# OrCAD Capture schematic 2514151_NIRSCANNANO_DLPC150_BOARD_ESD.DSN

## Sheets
1 PAGE-07 LAMP DRIVER: size A3
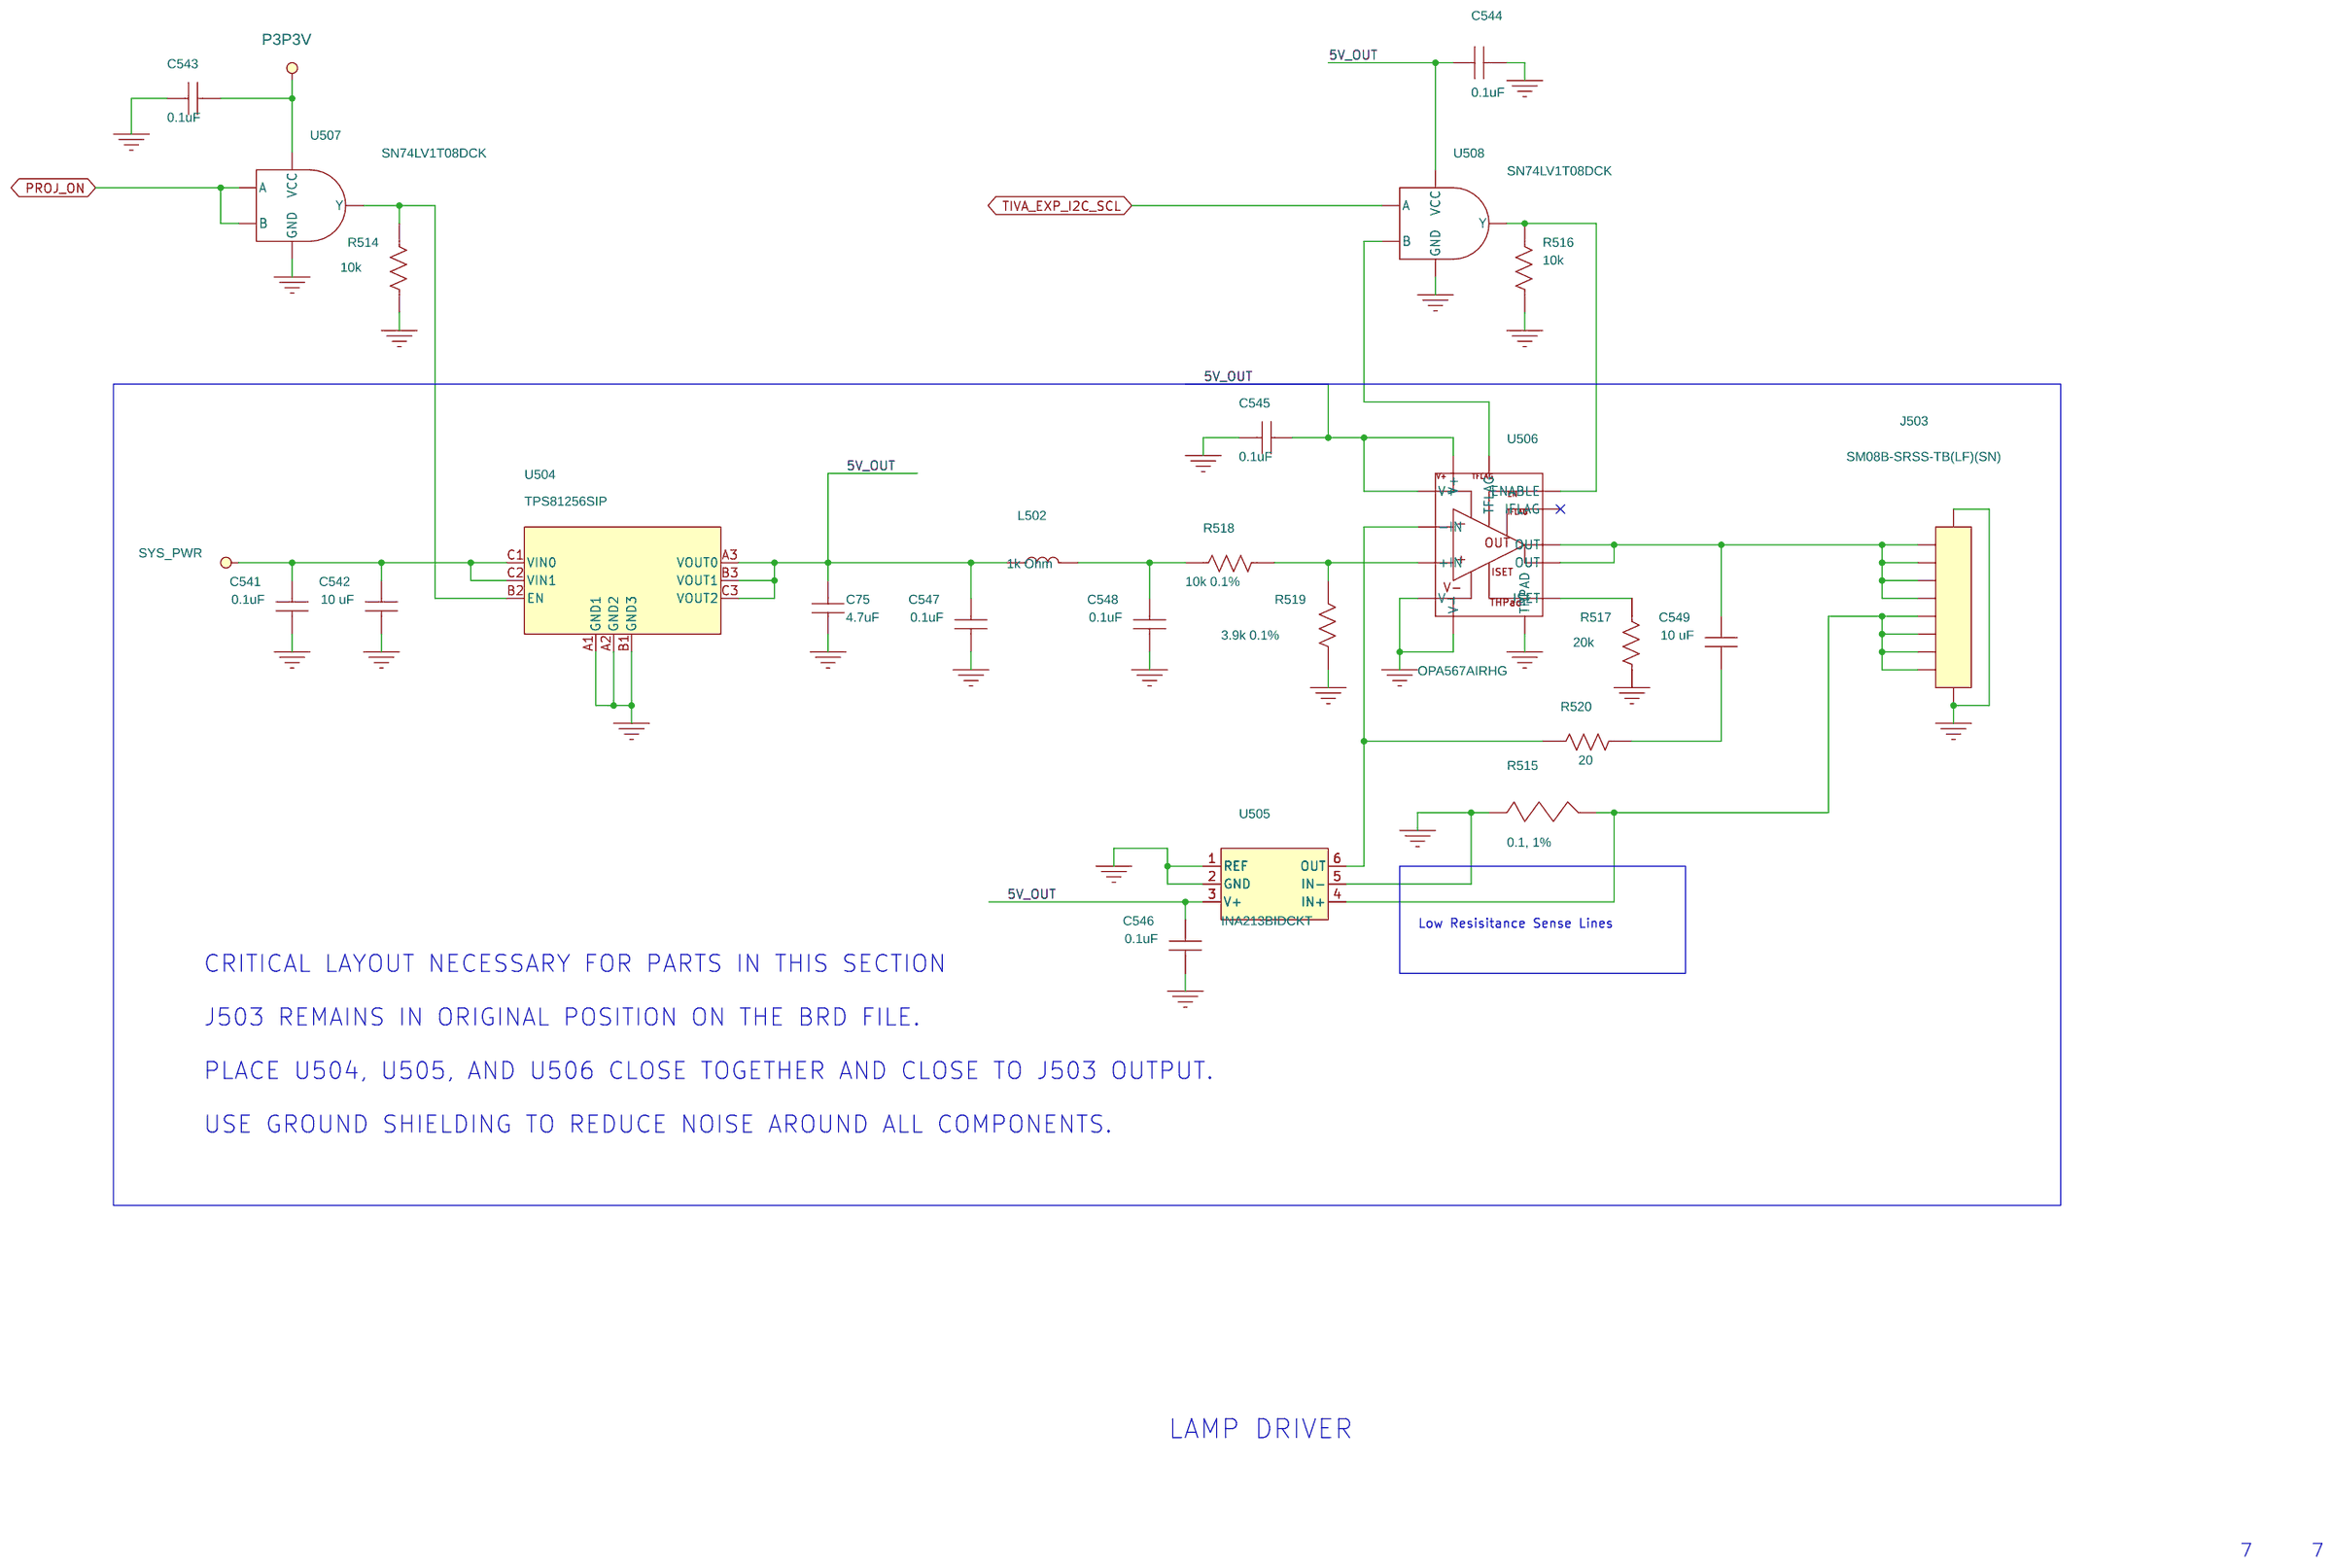
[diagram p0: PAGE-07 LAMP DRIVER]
2 PAGE-01 TITLE: title: ESD, NIRscan Nano DLPC 150 Board
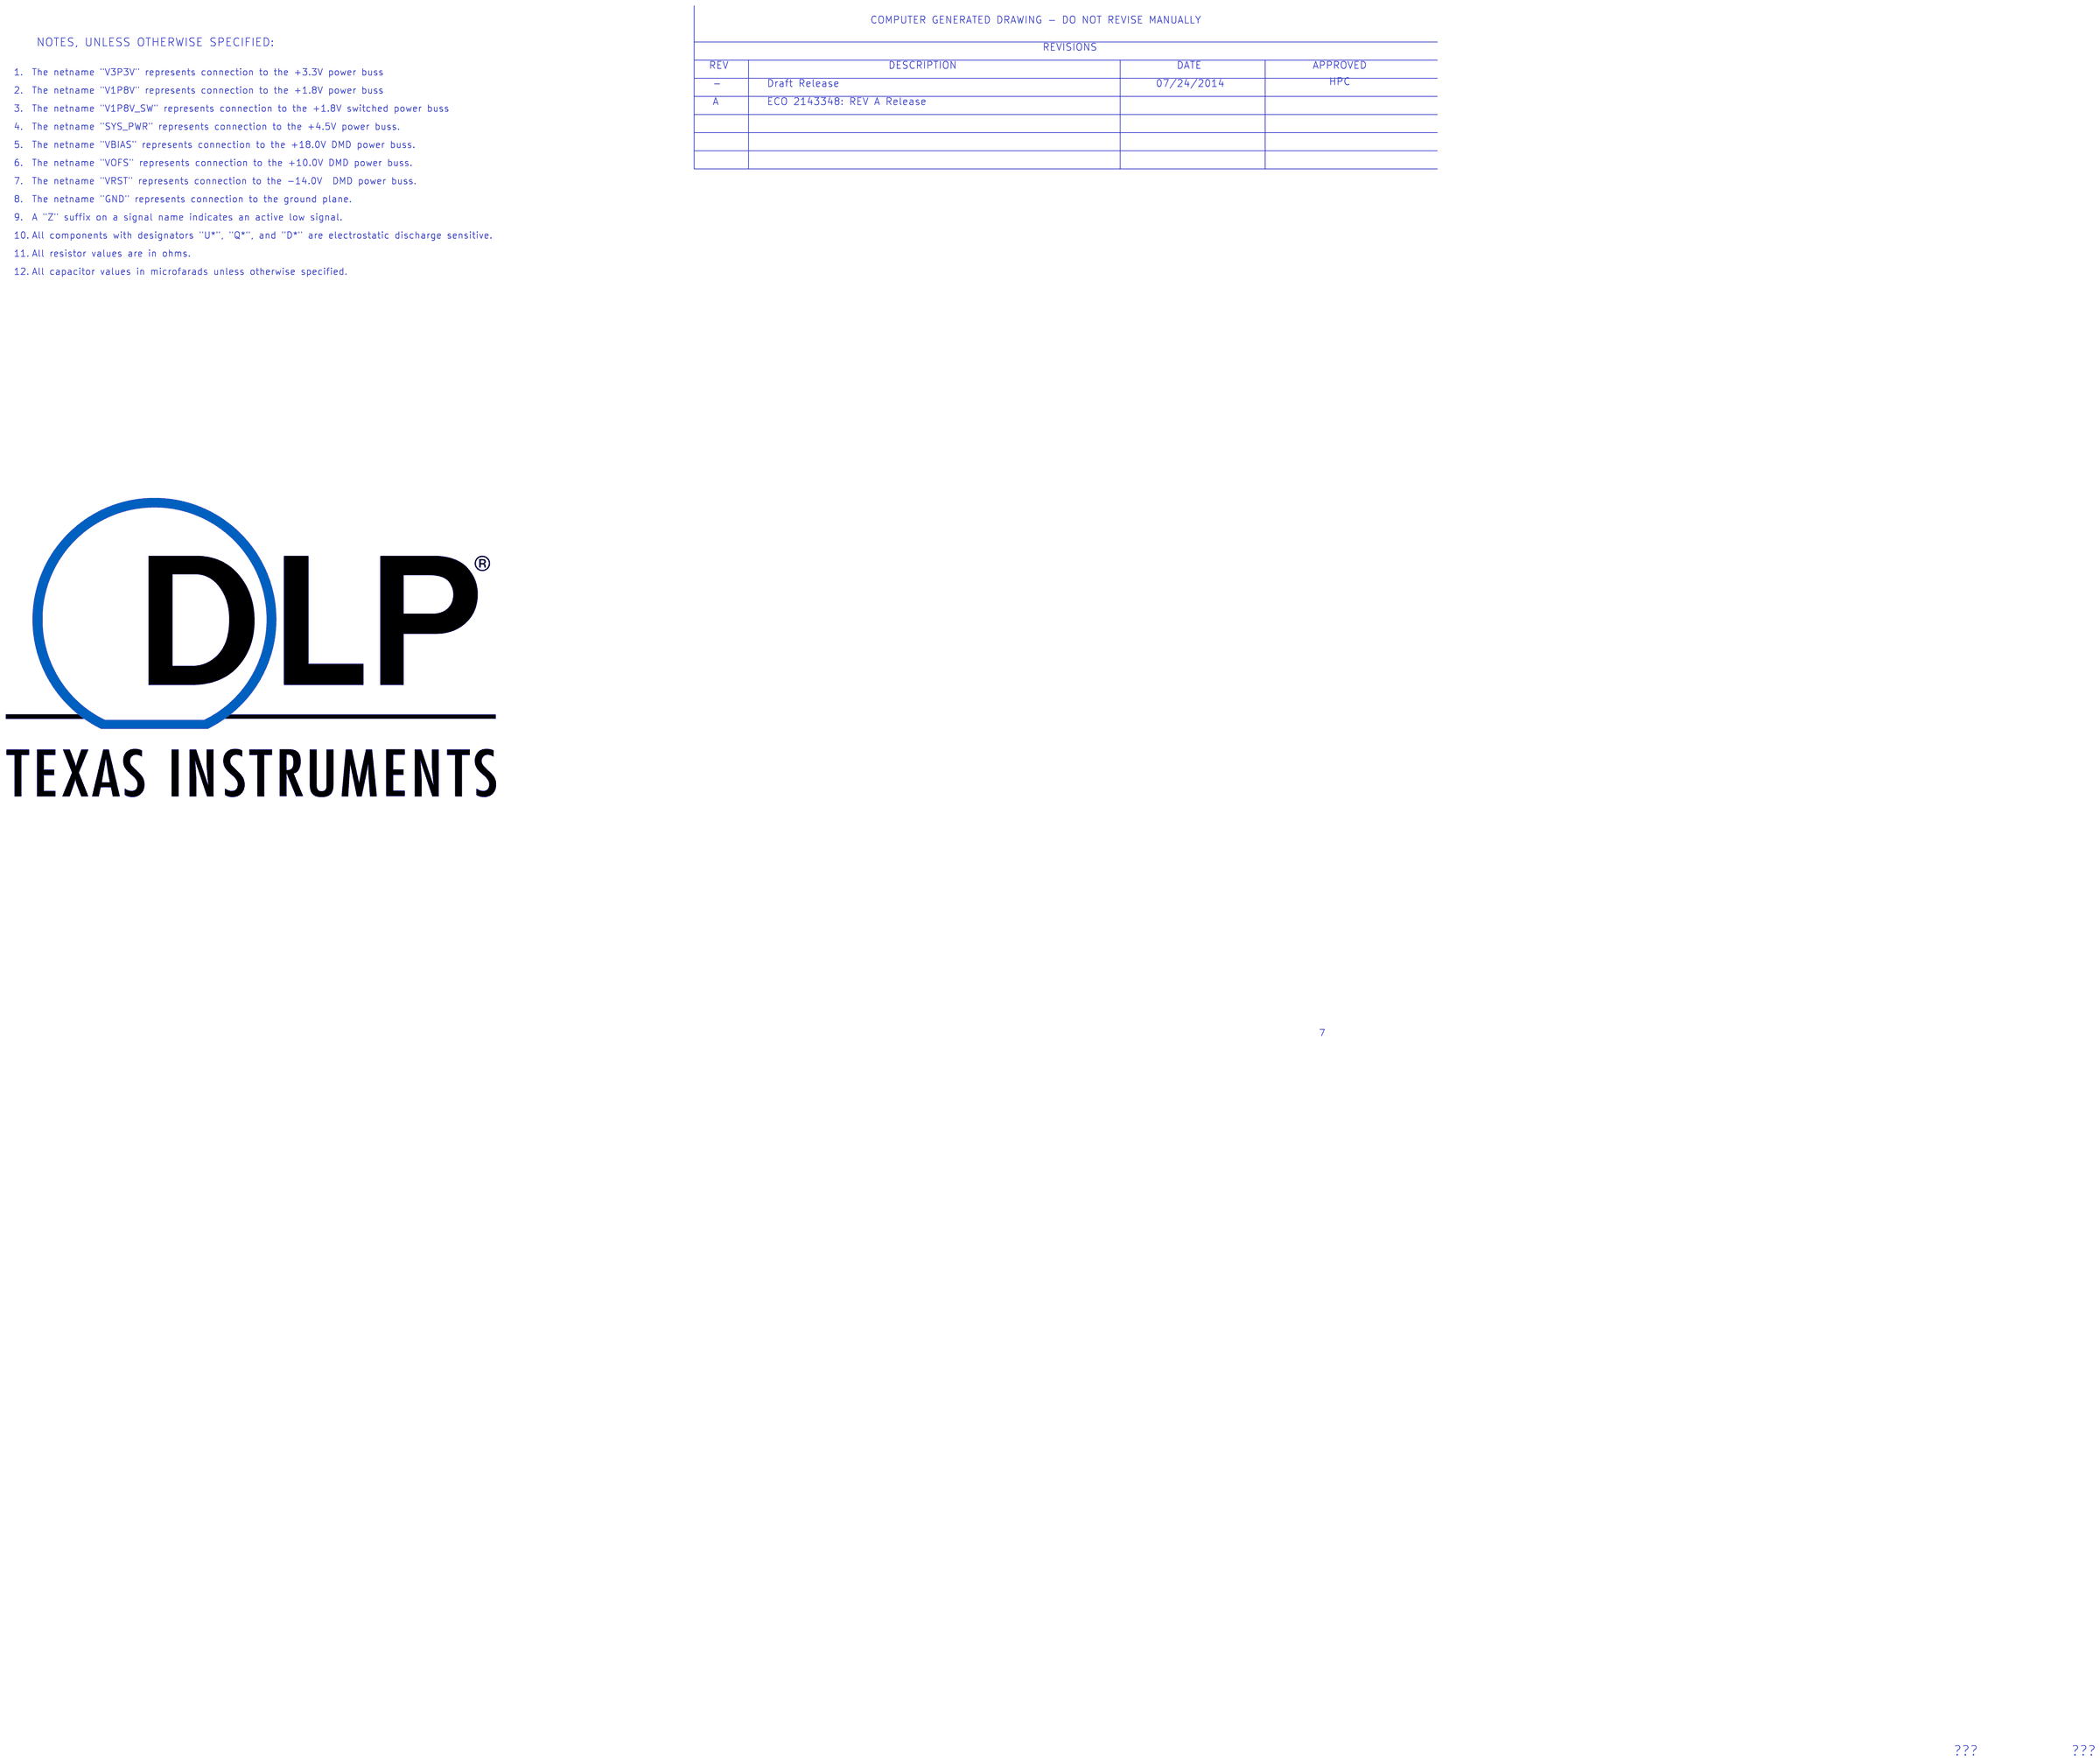
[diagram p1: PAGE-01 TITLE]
3 PAGE-02 DLPC PARALLEL & DMD: size A3
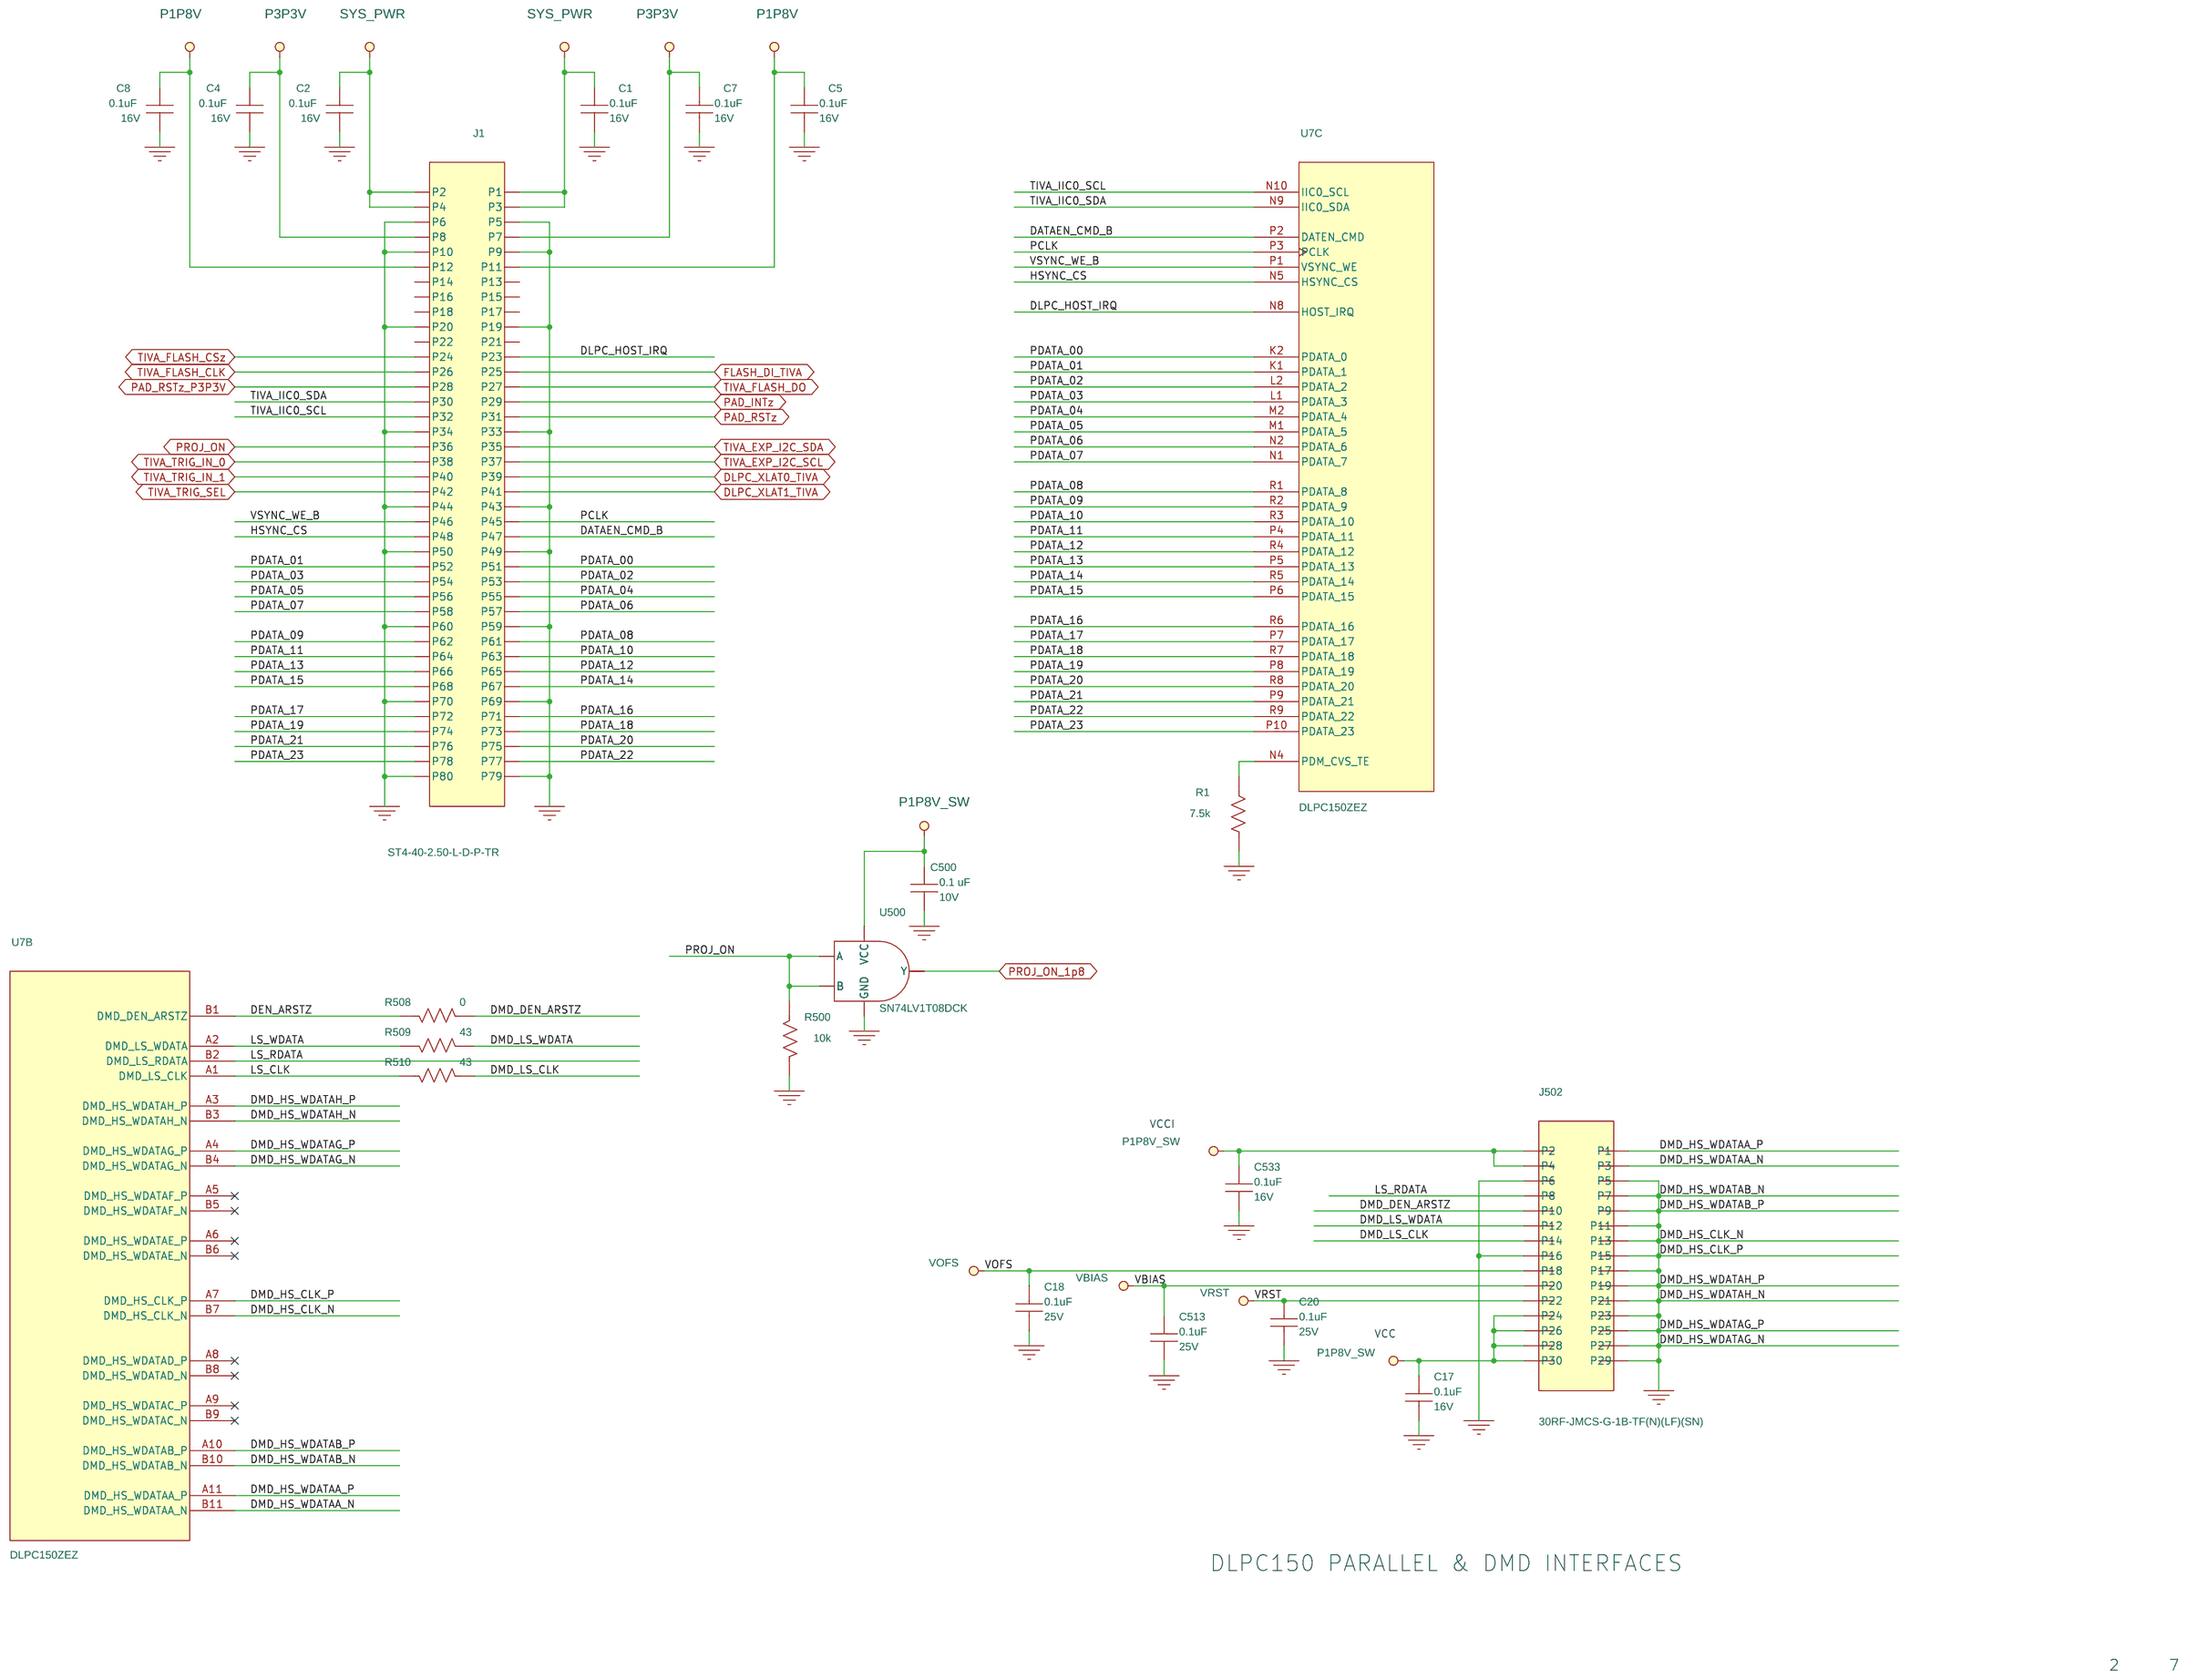
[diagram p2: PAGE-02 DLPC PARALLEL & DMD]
4 PAGE-04 DLPC POWER: size A3
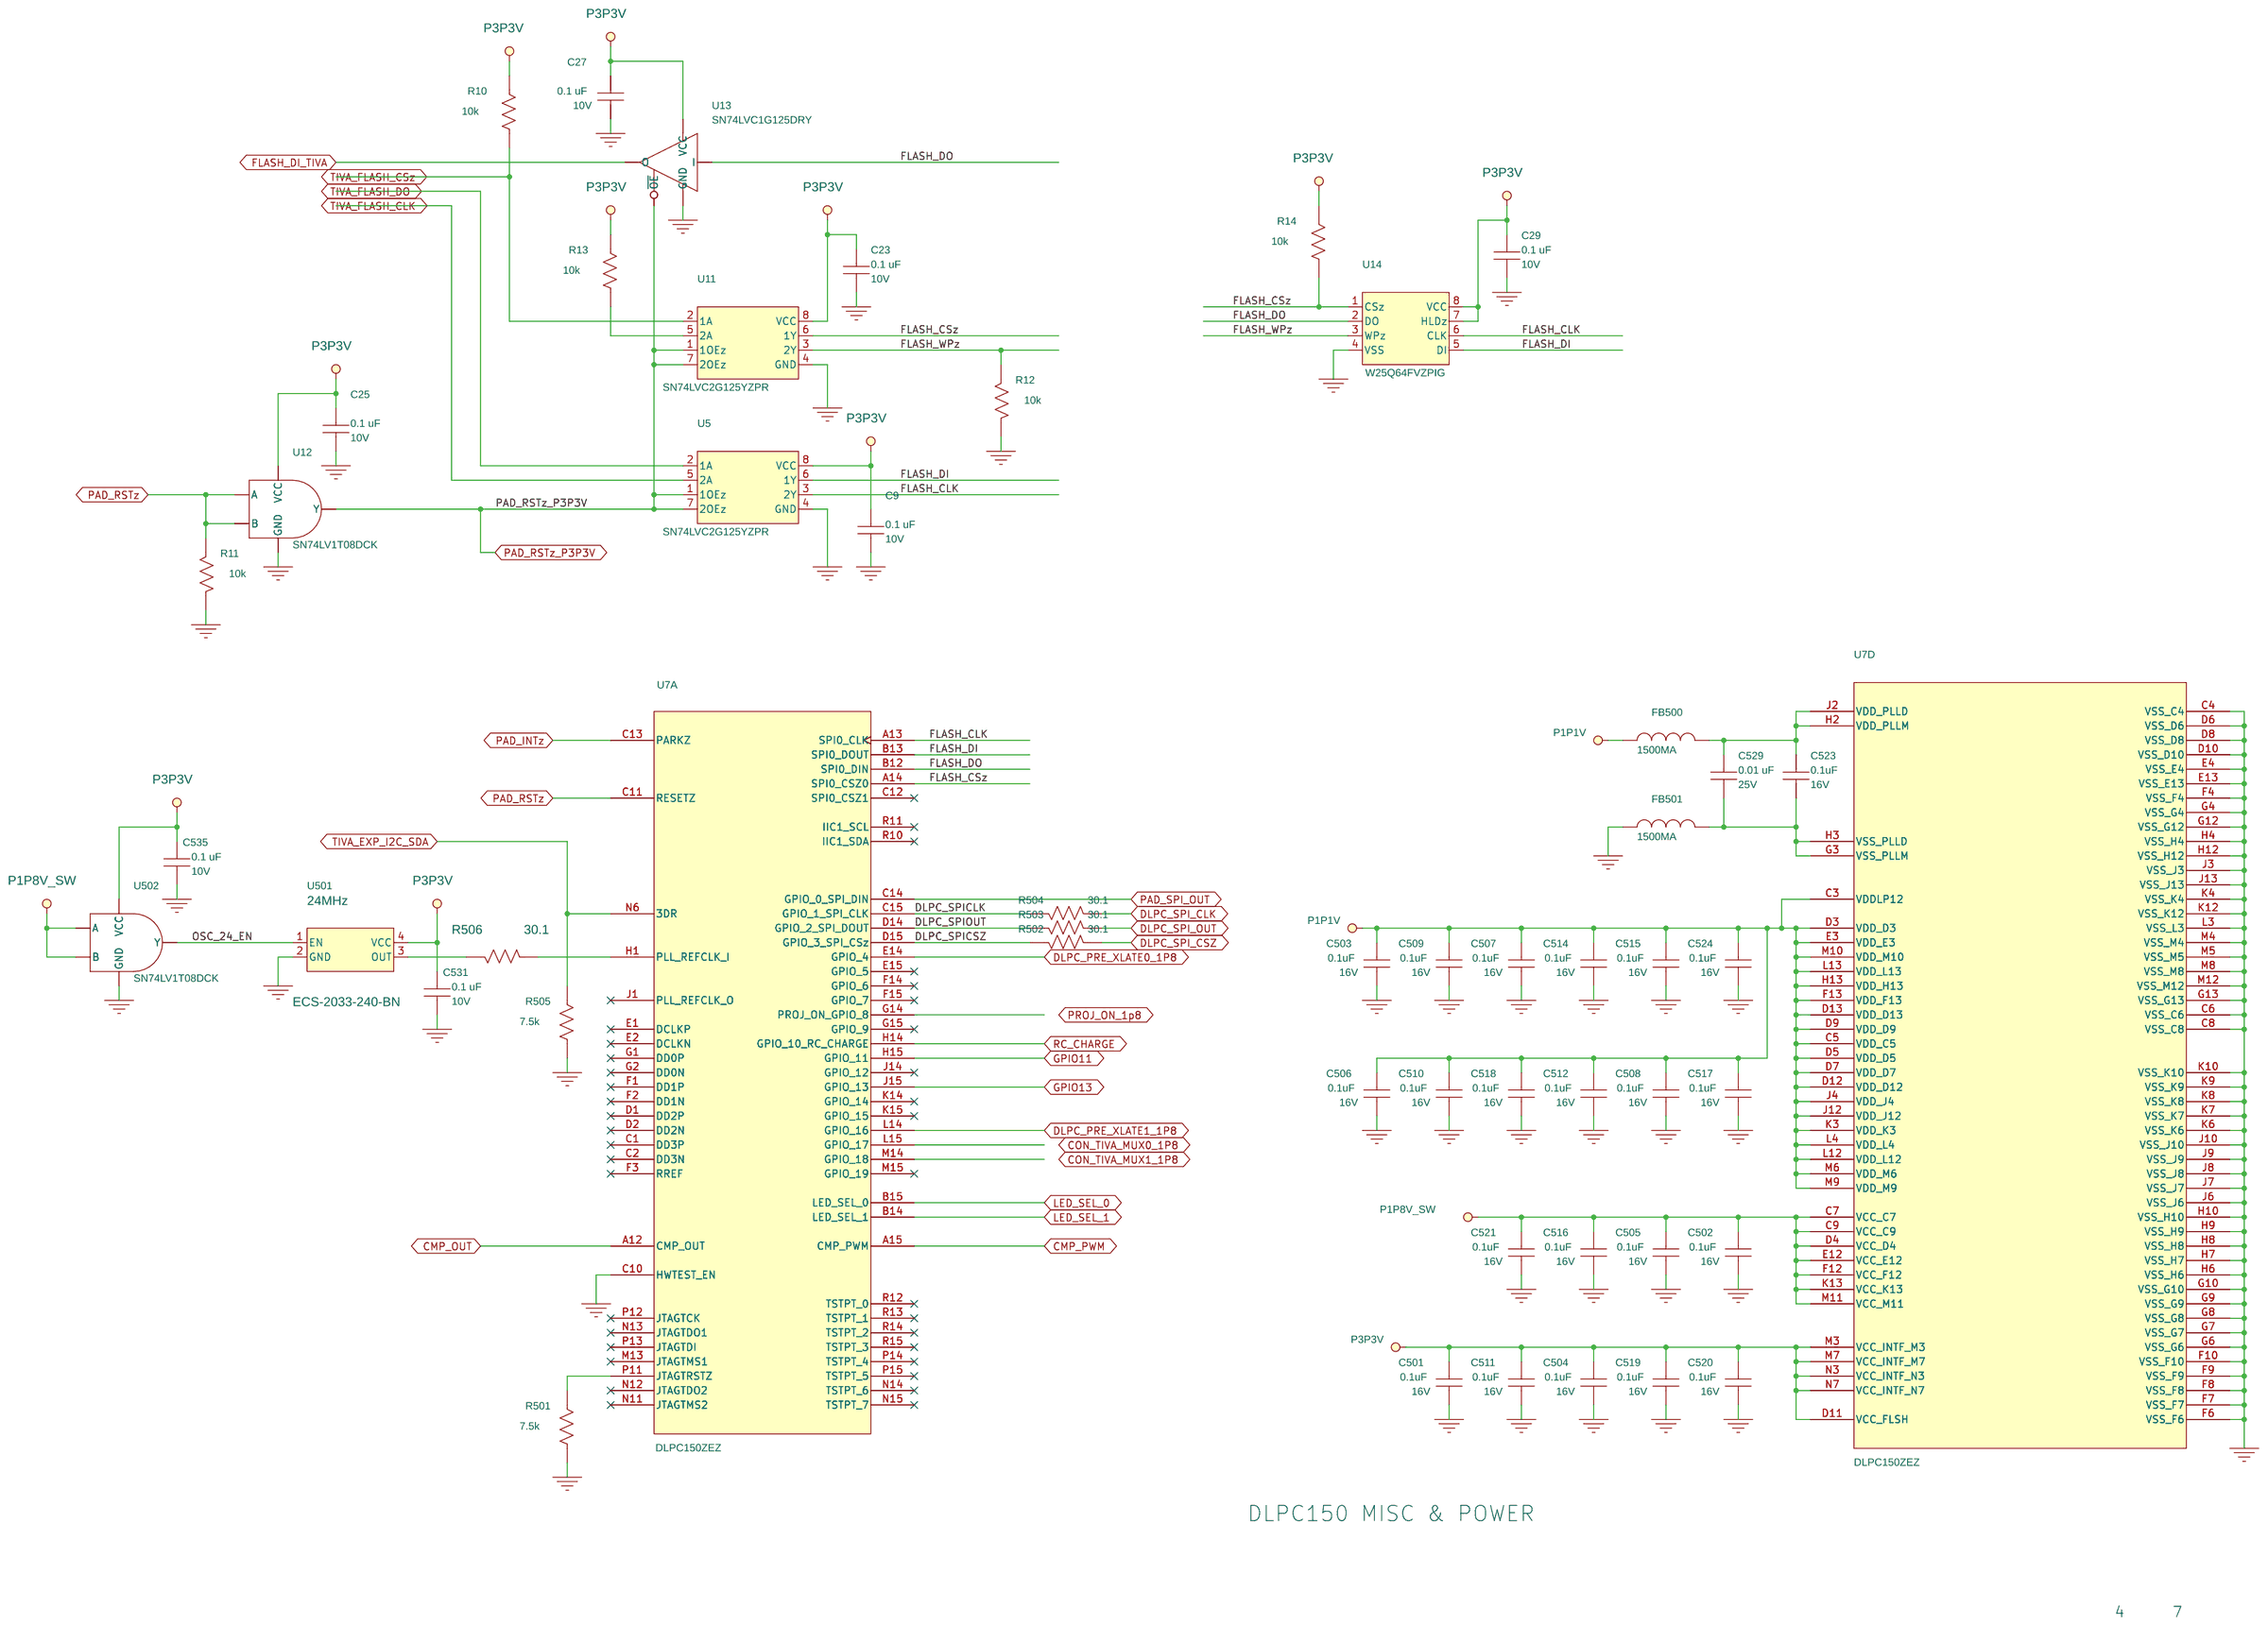
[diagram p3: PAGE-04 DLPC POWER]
5 PAGE-05 PAD_2005: size A3
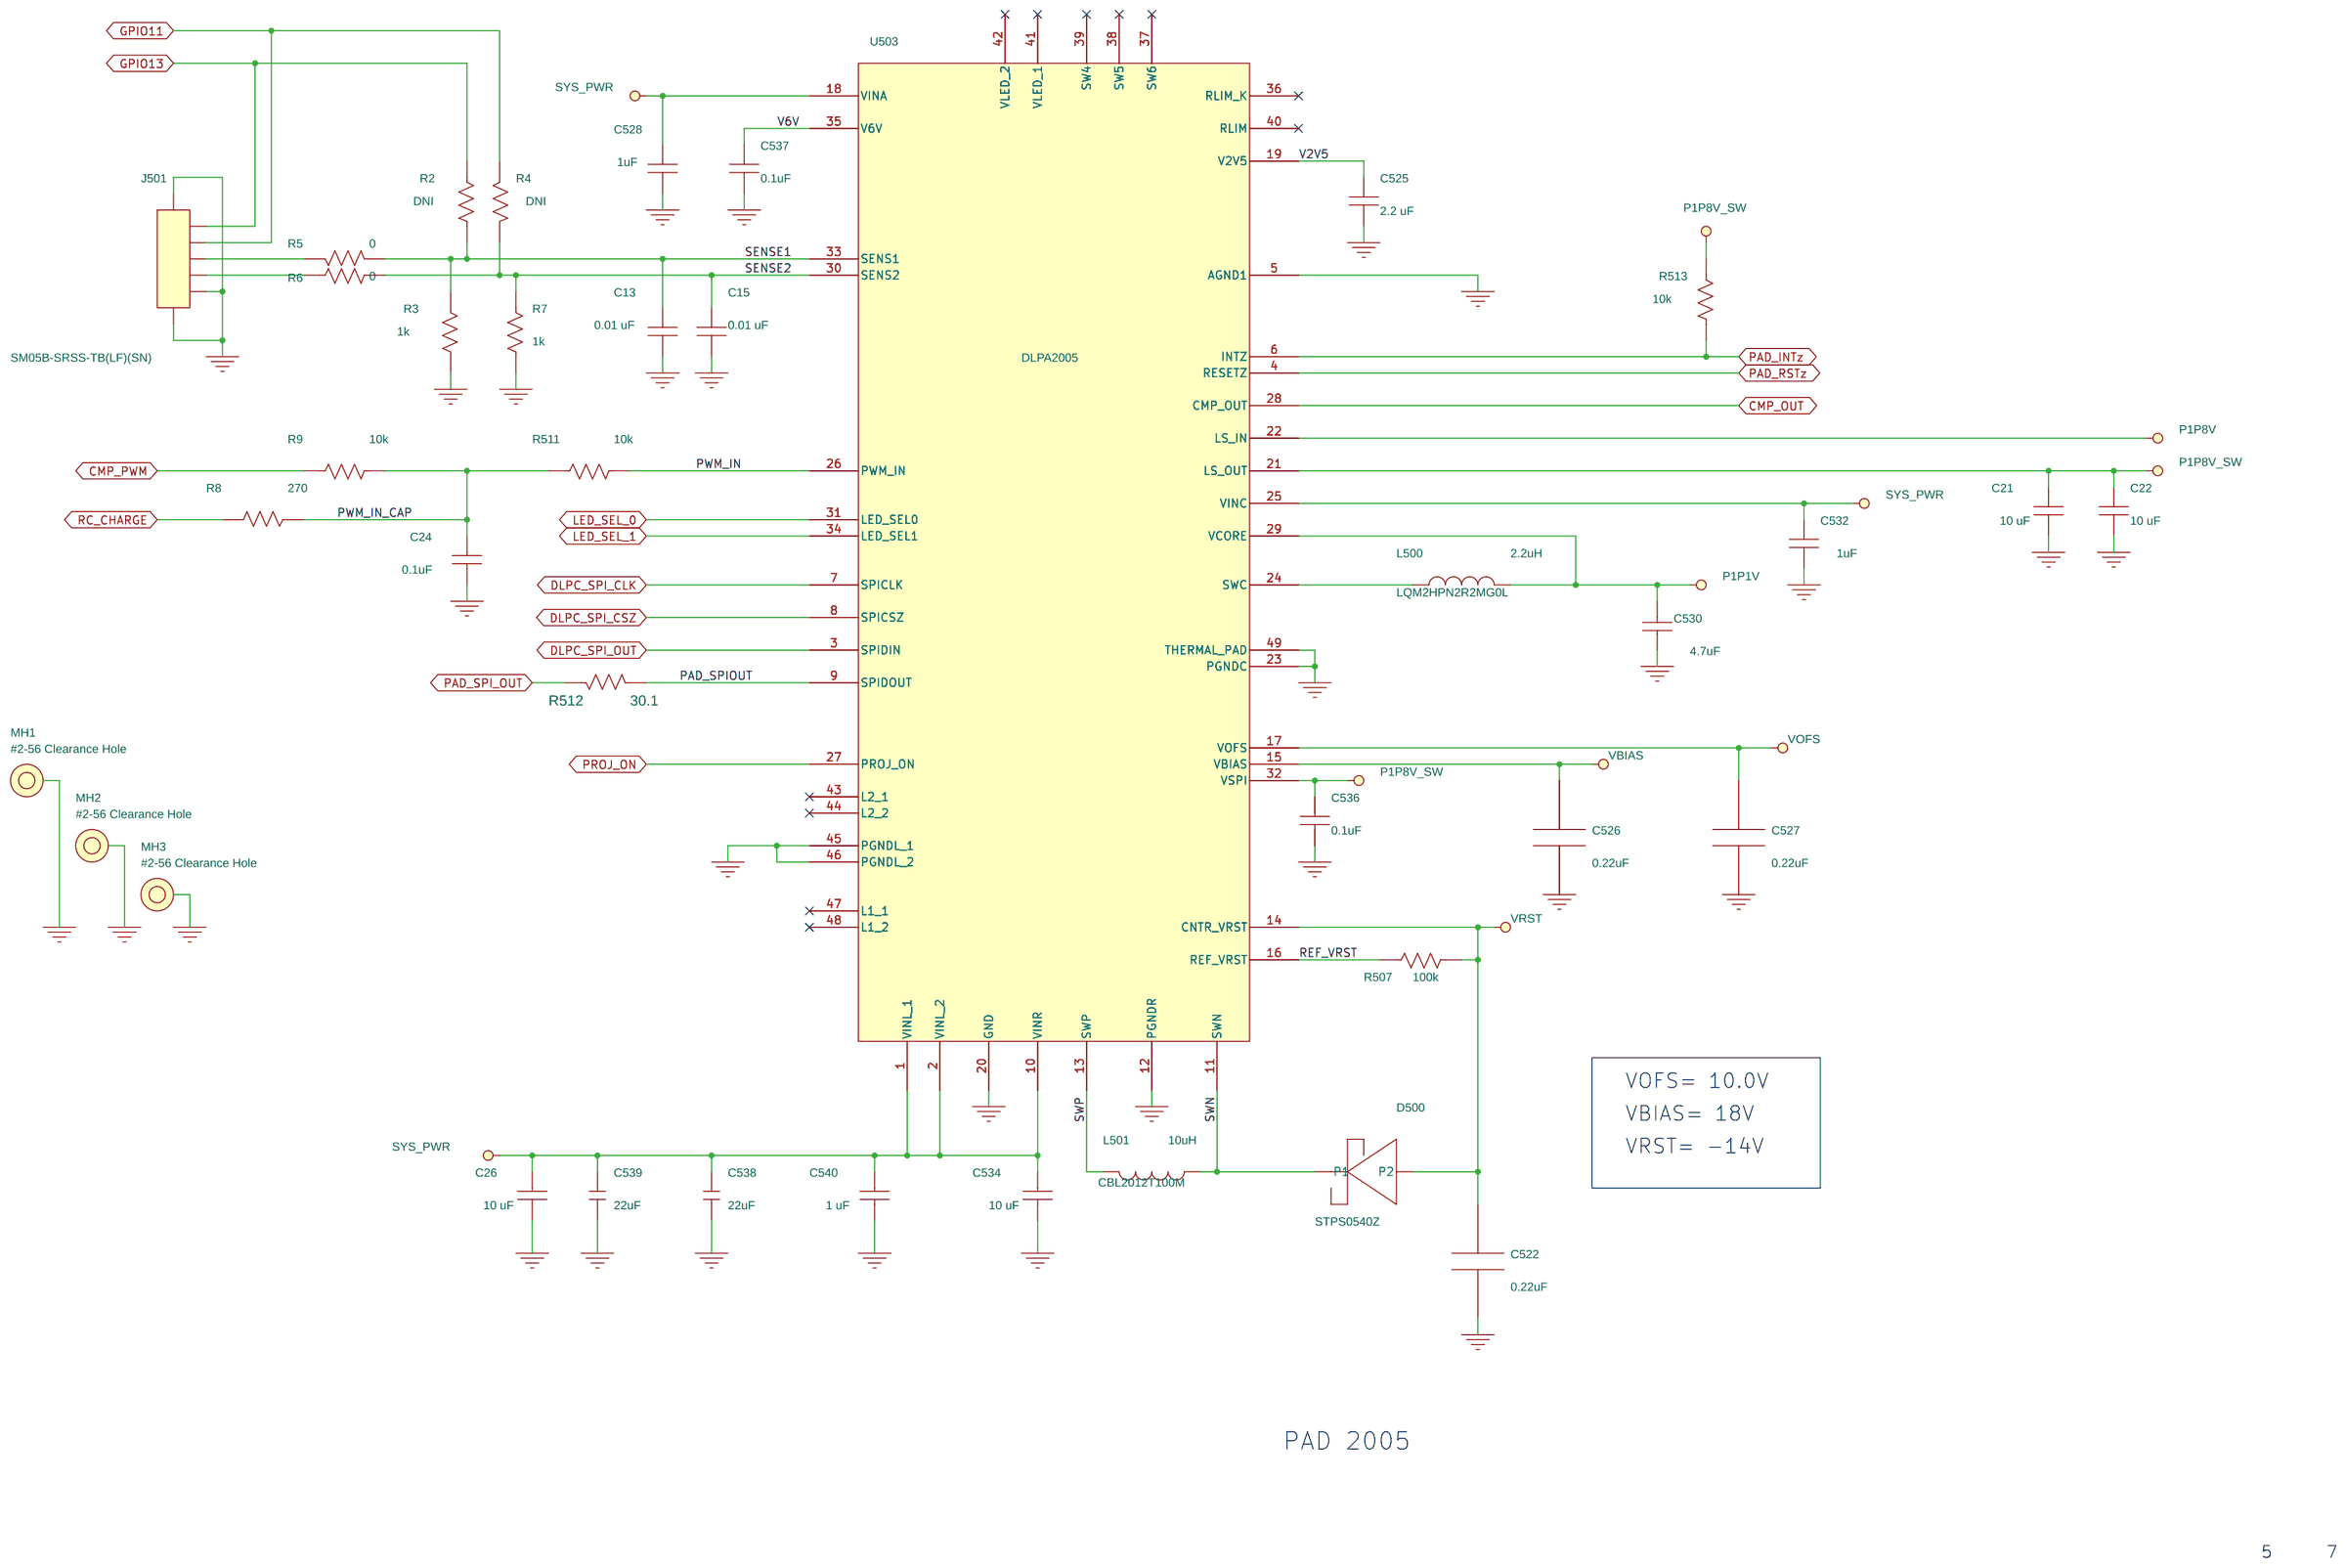
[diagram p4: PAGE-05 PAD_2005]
6 PAGE-06 REVISION HISTORY
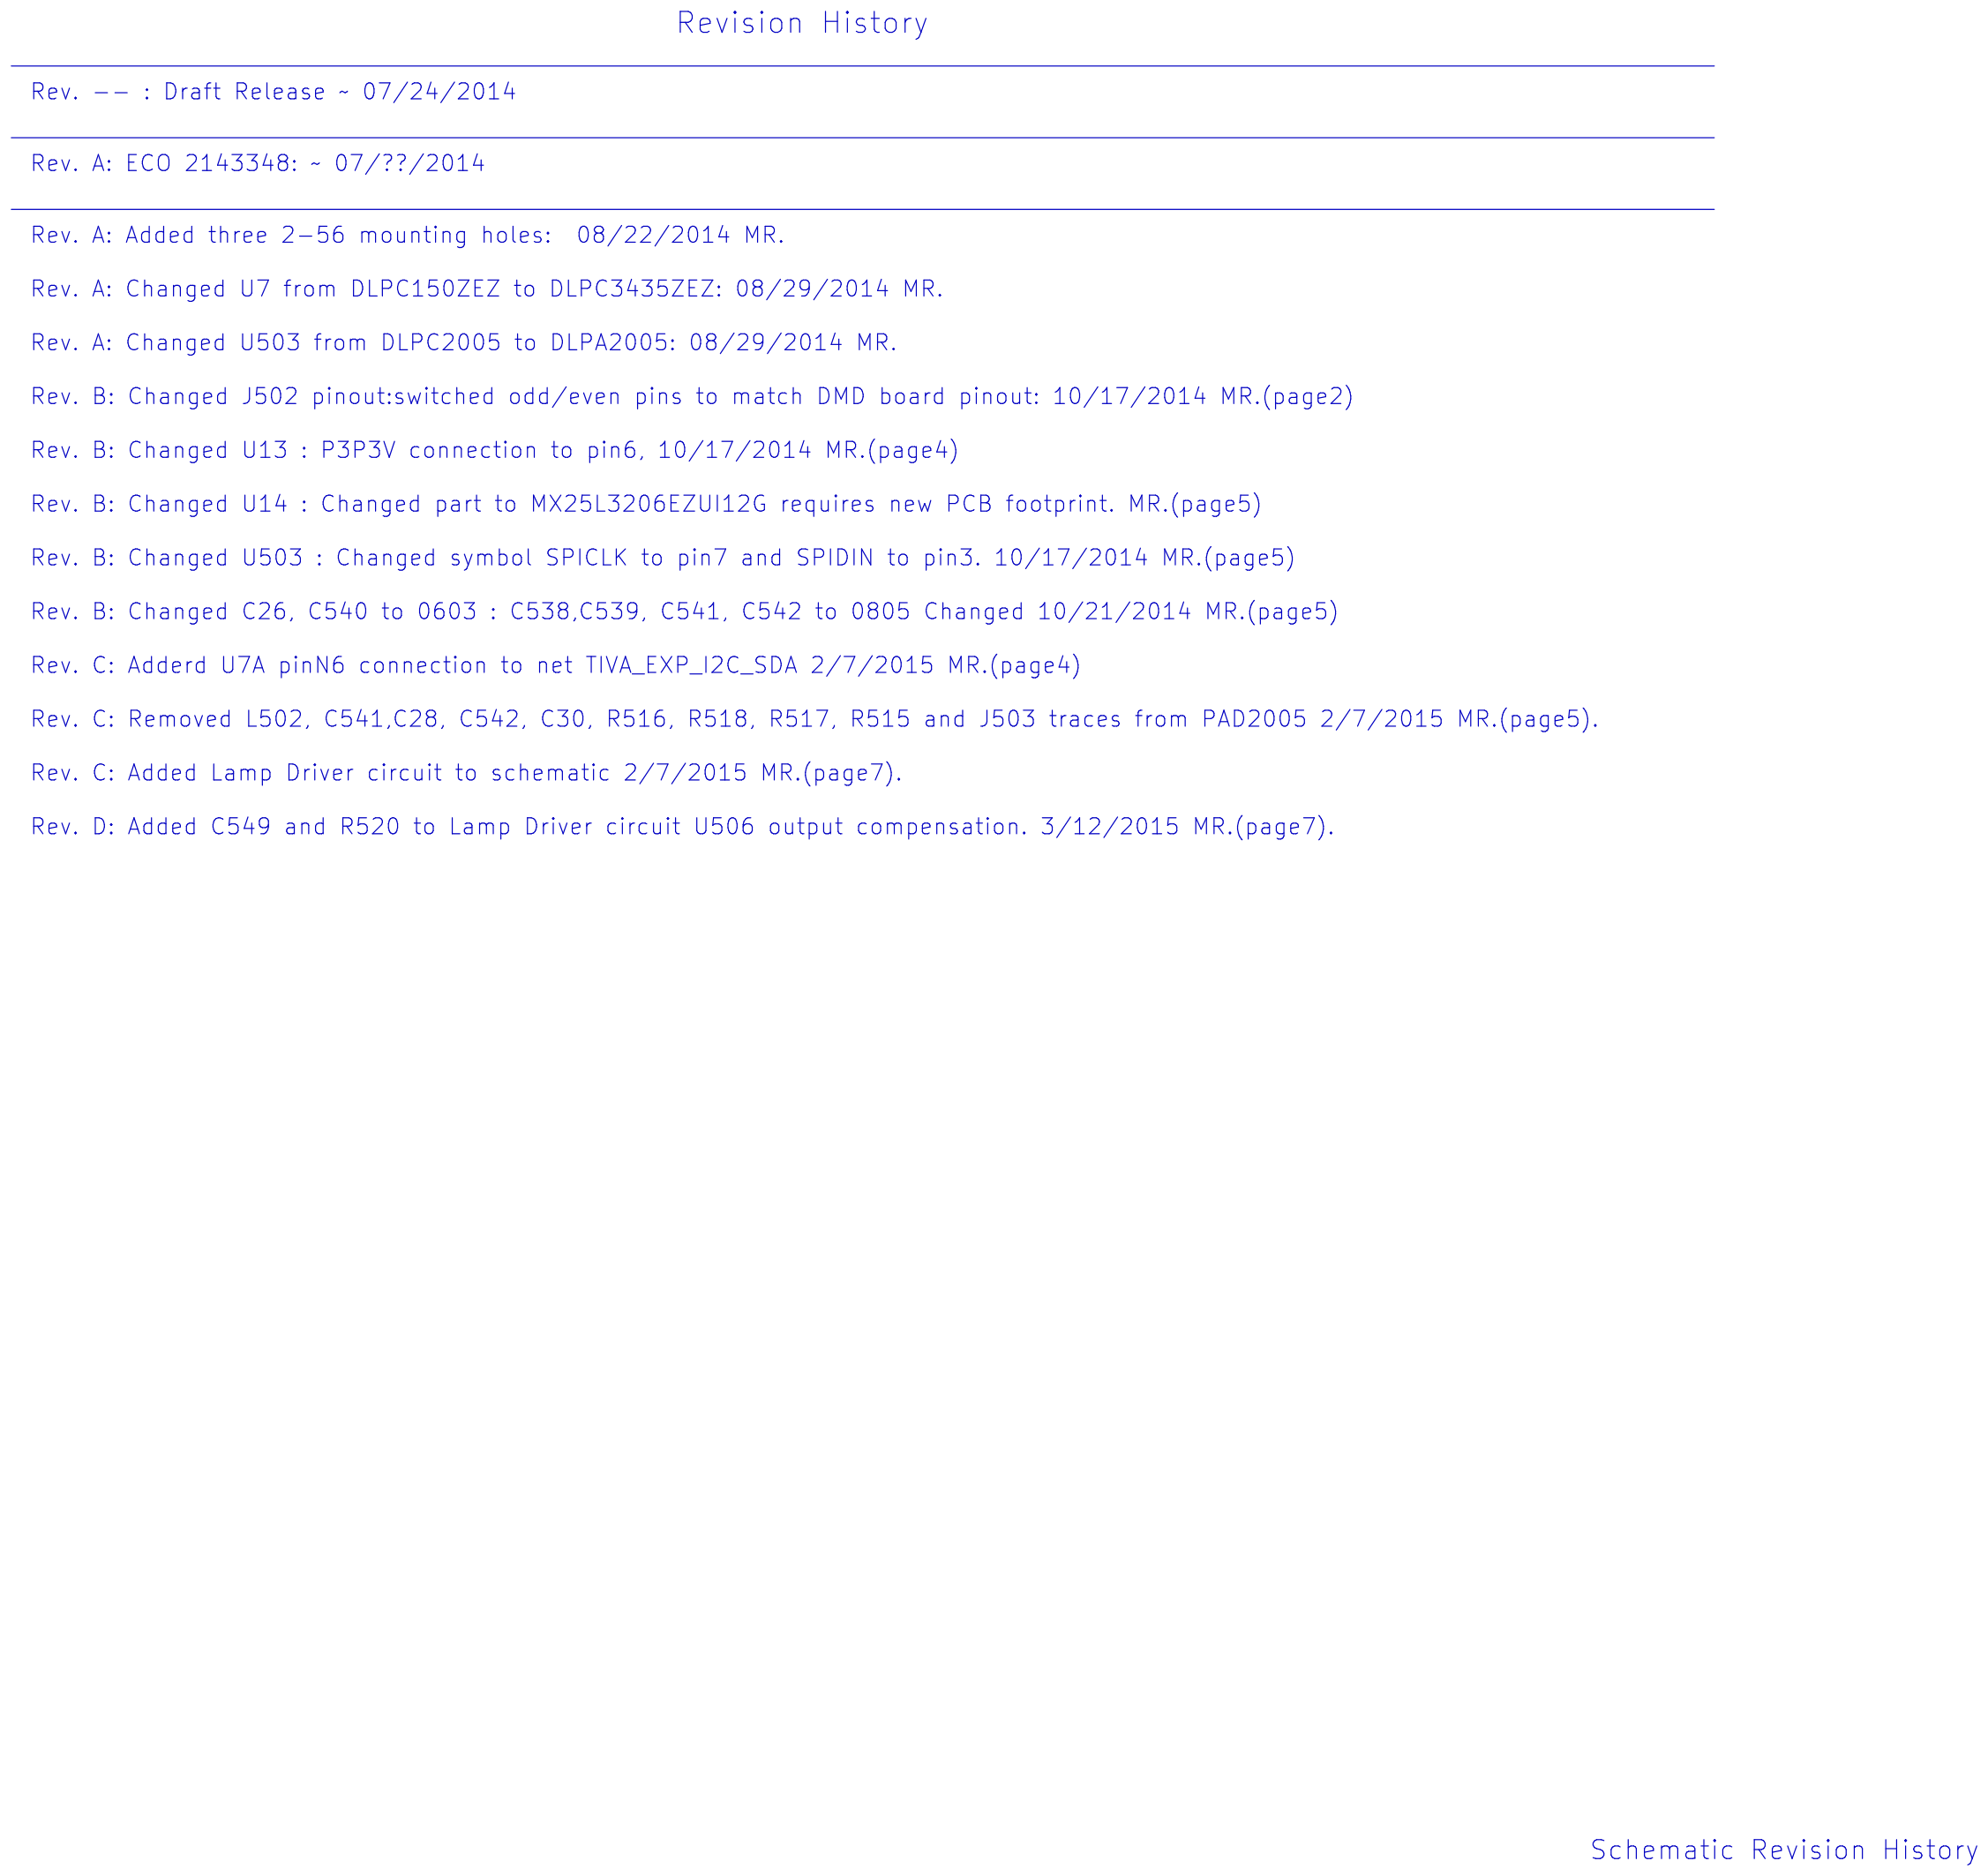
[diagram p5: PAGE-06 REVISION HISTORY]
7 PAGE-03 DLPC - I/O: size A3
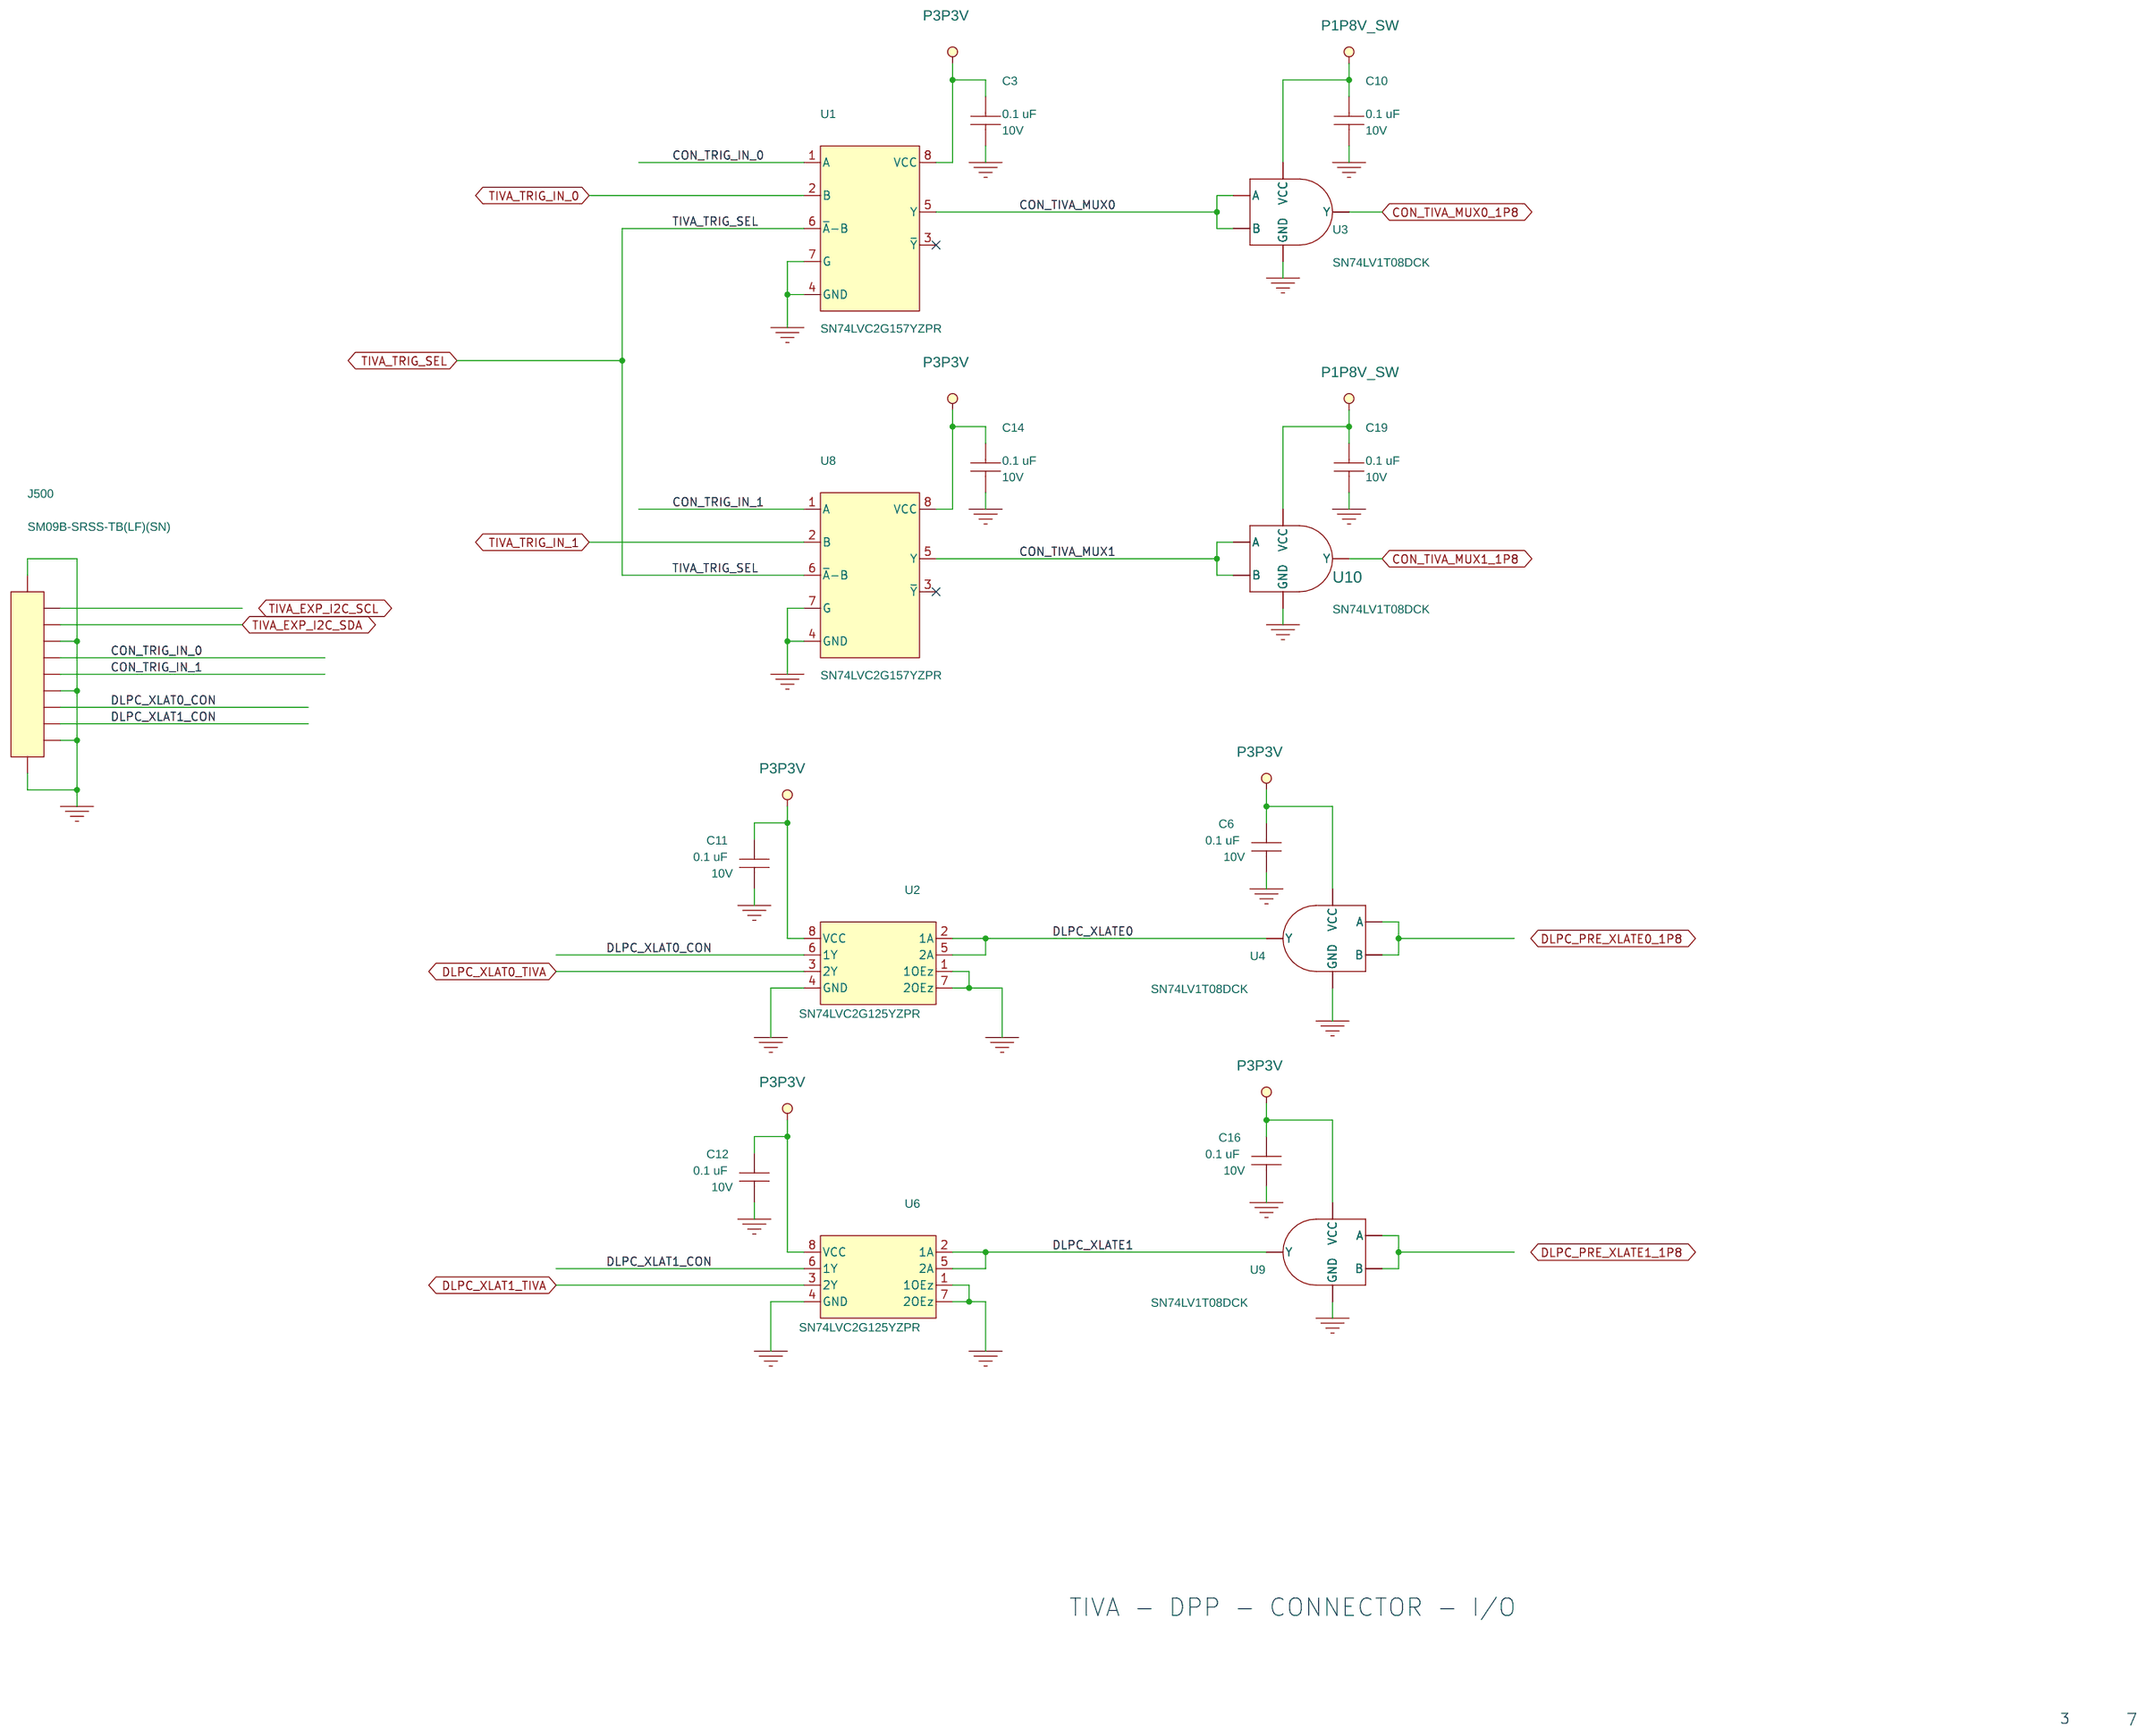
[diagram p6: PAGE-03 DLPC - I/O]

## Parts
sheet PAGE-02 DLPC PARALLEL & DMD
C1  0.1uF  [CAP_0402]
C2  0.1uF  [CAP_0402]
C4  0.1uF  [CAP_0402]
C5  0.1uF  [CAP_0402]
C7  0.1uF  [CAP_0402]
C8  0.1uF  [CAP_0402]
C17  0.1uF  [CAP_0402]
C18  0.1uF  [CAP_0402]
C20  0.1uF  [CAP_0402]
C500  0.1 uF  [CAP_0402]
C513  0.1uF  [CAP_0402]
C533  0.1uF  [CAP_0402]
J1  ST4-40-2.50-L-D-P-TR  [CONN60_MEC8_M]
J502  30RF-JMCS-G-1B-TF(N)(LF)(SN)  [CONN30_2x15]
R1  7.5k  [RES_0402]
R500  10k  [RES_0402]
R508  0  [RES_0201]
R509  43  [RES_0201]
R510  43  [RES_0201]
U7  DLPC150ZEZ  [13x13_VFBGA]  (sections A,B,C,D)
U500  SN74LV1T08DCK  [DCK]
sheet PAGE-03 DLPC - I/O
C3  0.1 uF  [CAP_0402]
C6  0.1 uF  [CAP_0402]
C10  0.1 uF  [CAP_0402]
C11  0.1 uF  [CAP_0402]
C12  0.1 uF  [CAP_0402]
C14  0.1 uF  [CAP_0402]
C16  0.1 uF  [CAP_0402]
C19  0.1 uF  [CAP_0402]
J500  SM09B-SRSS-TB(LF)(SN)  [1p0mm_CONN9]
U1  SN74LVC2G157YZPR  [YZP]
U2  SN74LVC2G125YZPR  [YZP]
U3  SN74LV1T08DCK  [DCK]
U4  SN74LV1T08DCK  [DCK]
U6  SN74LVC2G125YZPR  [YZP]
U8  SN74LVC2G157YZPR  [YZP]
U9  SN74LV1T08DCK  [DCK]
U10  SN74LV1T08DCK  [DCK]
sheet PAGE-04 DLPC POWER
C9  0.1 uF  [CAP_0402]
C23  0.1 uF  [CAP_0402]
C25  0.1 uF  [CAP_0402]
C27  0.1 uF  [CAP_0402]
C29  0.1 uF  [CAP_0402]
C501  0.1uF  [CAP_0402]
C502  0.1uF  [CAP_0402]
C503  0.1uF  [CAP_0402]
C504  0.1uF  [CAP_0402]
C505  0.1uF  [CAP_0402]
C506  0.1uF  [CAP_0402]
C507  0.1uF  [CAP_0402]
C508  0.1uF  [CAP_0402]
C509  0.1uF  [CAP_0402]
C510  0.1uF  [CAP_0402]
C511  0.1uF  [CAP_0402]
C512  0.1uF  [CAP_0402]
C514  0.1uF  [CAP_0402]
C515  0.1uF  [CAP_0402]
C516  0.1uF  [CAP_0402]
C517  0.1uF  [CAP_0402]
C518  0.1uF  [CAP_0402]
C519  0.1uF  [CAP_0402]
C520  0.1uF  [CAP_0402]
C521  0.1uF  [CAP_0402]
C523  0.1uF  [CAP_0402]
C524  0.1uF  [CAP_0402]
C529  0.01 uF  [CAP_0402]
C531  0.1 uF  [CAP_0402]
C535  0.1 uF  [CAP_0402]
FB500  1500MA  [FB_0402]
FB501  1500MA  [FB_0402]
R10  10k  [RES_0402]
R11  10k  [RES_0402]
R12  10k  [RES_0402]
R13  10k  [RES_0402]
R14  10k  [RES_0402]
R501  7.5k  [RES_0402]
R502  30.1  [RES_0402]
R503  30.1  [RES_0402]
R504  30.1  [RES_0402]
R505  7.5k  [RES_0402]
R506  30.1  [RES_0402]
U5  SN74LVC2G125YZPR  [YZP]
U11  SN74LVC2G125YZPR  [YZP]
U12  SN74LV1T08DCK  [DCK]
U13  SN74LVC1G125DRY  [DRY]
U14  W25Q64FVZPIG  [8-WSON]
U501  24MHz  [2p5mm_x_2p0mm]
U502  SN74LV1T08DCK  [DCK]
sheet PAGE-05 PAD_2005
C13  0.01 uF  [CAP_0402]
C15  0.01 uF  [CAP_0402]
C21  10 uF  [CAP_0402]
C22  10 uF  [CAP_0402]
C24  0.1uF  [CAP_0402]
C26  10 uF  [CAP_0603]
C522  0.22uF  [CAP_0402]
C525  2.2 uF  [CAP_0402]
C526  0.22uF  [CAP_0402]
C527  0.22uF  [CAP_0402]
C528  1uF  [CAP_0402]
C530  4.7uF  [CAP_0402]
C532  1uF  [CAP_0402]
C534  10 uF  [CAP_0603]
C536  0.1uF  [CAP_0402]
C537  0.1uF  [CAP_0402]
C538  22uF  [0805]
C539  22uF  [0805]
C540  1 uF  [CAP_0603]
D500  STPS0540Z  [SOD_123]
J501  SM05B-SRSS-TB(LF)(SN)  [1p0mm_CONN5]
L500  2.2uH  [1008_2p5mmx2mm]
L501  10uH  [0805]
MH1  #2-56 Clearance Hole  [pl_mtg_2_56_89d_260c]
MH2  #2-56 Clearance Hole  [pl_mtg_2_56_89d_260c]
MH3  #2-56 Clearance Hole  [pl_mtg_2_56_89d_260c]
R2  DNI  [RES_0402]
R3  1k  [RES_0402]
R4  DNI  [RES_0402]
R5  0  [RES_0201]
R6  0  [RES_0201]
R7  1k  [RES_0402]
R8  270  [RES_0402]
R9  10k  [RES_0402]
R507  100k  [RES_0402]
R511  10k  [RES_0402]
R512  30.1  [RES_0402]
R513  10k  [RES_0402]
U503  DLPA2005  [QFN-48]
sheet PAGE-07 LAMP DRIVER
C75  4.7uF  [CAP_0402]
C541  0.1uF  [CAP_0402]
C542  10 uF  [CAP_0603]
C543  0.1uF  [CAP_0402]
C544  0.1uF  [CAP_0402]
C545  0.1uF  [CAP_0402]
C546  0.1uF  [CAP_0402]
C547  0.1uF  [CAP_0402]
C548  0.1uF  [CAP_0402]
C549  10 uF  [CAP_0603]
J503  SM08B-SRSS-TB(LF)(SN)  [CONN8_1p0mm]
L502  1k Ohm  [0402]
R514  10k  [RES_0402]
R515  0.1, 1%  [0603]
R516  10k  [RES_0402]
R517  20k  [RES_0402]
R518  10k 0.1%  [RES_0402]
R519  3.9k 0.1%  [RES_0402]
R520  20  [RES_0402]
U504  TPS81256SIP  [9USIP]
U505  INA213BIDCKT  [SC70-6]
U506  OPA567AIRHG  [pcb]
U507  SN74LV1T08DCK  [DCK]
U508  SN74LV1T08DCK  [DCK]

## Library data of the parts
C1 C2 C4 C5 C7 C8 C17 C24 C533 C536 C537 C541 C543-C548 = CAP_NP: CAP CER 0.1UF 16V 10% X7R 0402; MFG: Murata; Manufacturer: Murata; Part Number: GRM155R71C104KA88D; RATING: 16V; SOURCE: DIGI 490-3261-1-ND; TOLERANCE: 10%; Type: X7R; VPC: 16V
C18 C513 = CAP_NP: CAP CER 0.1UF 25V 10% X5R 0402; MFG: Taiyo Yuden; Manufacturer: Taiyo Yuden; Part Number: TMK105BJ104KV-F; RATING: 25V; SOURCE: DIGI 587-1456-1-ND; TOLERANCE: 10%; Type: X7R; VPC: 25V
C20 = CAP_NP: CAP CER 0.1UF 25V 10% X5R 0402; MFG: Taiyo Yuden; Manufacturer: Taiyo Yuden; Part Number: TMK105BJ104KV-F; RATING: 25V; SOURCE: DIGI 587-1456-1-ND; TOLERANCE: 10%; Type: X5R; VPC: 25V
C3 C6 C9-C12 C14 C16 C19 C23 C25 C27 C500 C535 = CAP_NP: CAP CER 0.1UF 10V 10% X7R 0402; MFG: KEMET; Manufacturer: KEMET; Part Number: C0402C104K8RACTU; RATING: 10V; SOURCE: DIGI 399-3520-1-ND; TOLERANCE: 10%; Type: X7R
J1 = CONN80_MEC8_M_0_PIN
J502 = CONN30_2x15_short: CONN 30POS RECEPTACLE W/BOSSES; Manufacturer: JST; SOURCE: DIGI 455-2839CT-ND
R1 R501 R505 = PAS,R,large: RES 7.5K OHM 1/10W 1% 0402 SMD; Family: passive; Index PN: 680; Lead Style: SMT; MFG: Panasonic; Manufacturer: Panasonic; Material: chip; P/D_NUM: ERJ-2RKF7501X; Part Number: ERJ-2RKF7501X; Power: 1/16W; SOURCE: DIGI P7.50KLCT-ND; Tolerance: 1%; Type: resistor; VPC: 1/16W; Vendor: Panasonic
R11 R500 R513 = PAS,R,large: RES 10K OHM 1/10W 1% 0402 SMD; Family: passive; Index PN: 680; Lead Style: SMT; MFG: Panasonic; Manufacturer: Panasonic; Material: chip; P/D_NUM: ERJ-2RKF1002X; Part Number: ERJ-2RKF1002X; Power: 1/16W; SOURCE: DIGI P10.0KLCT-ND; Tolerance: 1%; Type: resistor; VPC: 1/16W; Vendor: Panasonic
R5 R6 R508 = PAS,R,large: RES 0.0 OHM 1/20W JUMP 0201 SMD; Family: passive; Index PN: 1178; Lead Style: SMT; MFG: Panasonic; Manufacturer: Panasonic; Material: chip; P/D_NUM: ERJ-1GE0R00C; Part Number: ERJ-1GE0R00C; SOURCE: DIGI P0.0AGCT-ND; Type: resistor; VENDOR: Panasonic; VPC: 1/20W
R509 R510 = PAS,R,large: RES 43 OHM 1/20W 5% 0201 SMD; DigiKey: P43AGCT-ND; DigiReel: P43AGDKR-ND; Family: passive; Index PN: 1167; Lead Style: SMT; MFG: Panasonic; Manufacturer: Panasonic; P/D_NUM: ERJ-1GEJ430C; Part Number: ERJ-1GEJ430C; Part Specific: RES 43 OHM 1/20W 5% 0201 SMD; SOURCE: DIGI P43AGCT-ND; TOLERANCE: 5%; Type: resistor; VENDOR: Panasonic
U7 = DLPC150ZEZ_0: Part Number: DLPC3435ZEZ
U3 U4 U9 U10 U12 U500 U502 U507 U508 = SN74LV1T08: Source: MOUSER 595-SN74LV1T08DCKR
J500 = CONN_9n_1p0mm: CONN HEADER SH 9POS SIDE 1MM TIN; Manufacturer: JST; SOURCE: DIGI 455-1809-1-ND
U1 U8 = SN74LVC2G157: IC SNGL 2TO1 DATA SELECT 8-DSBGA; Manufacturer: Texas Instruments; Source: DIGI 296-18804-1-ND
U2 U5 U6 U11 = SN74LVC2G125: IC BUS BUFF TRI-ST DL 8DSBGA; SOURCE: DIGI 296-15109-1-ND
C29 C531 = CAP_NP: CAP CER 0.1UF 10V 10% X7R 0402; Manufacturer: KEMET; Part Number: C0402C104K8RACTU; RATING: 10V; SOURCE: DIGI 399-3520-1-ND; TOLERANCE: 10%; Type: X7R
C501-C512 C514-C521 C523 C524 = CAP_NP: CAP CER 0.1UF 16V 10% X7R 0402; Manufacturer: Murata; Part Number: GRM155R71C104KA88D; RATING: 16V; SOURCE: DIGI 490-3261-1-ND; TOLERANCE: 10%; Type: X7R; VPC: 16V
C529 = CAP_NP: CAP CER 10000PF 25V 10% X5R 0402; Manufacturer: TDK; Part Number: C1005X5R1E103K050BA; RATING: 25V; SOURCE: DIGI 445-7386-1-ND; TOLERANCE: 10%; Type: X5R
FB500 FB501 = PAS,INDUCTOR: FERRITE CHIP 80 OHM 1500MA 0402; Manufacturer: MURATA; Part Number: BLM15PD800SN1D; SOURCE: DIGI 490-5202-1-ND
R10 R12-R14 R511 R514 R516 = PAS,R,large: RES 10K OHM 1/10W 1% 0402 SMD; DigiKey: P10.0KLCT-ND; DigiReel: P10.0KLDKR-ND; Family: passive; Index PN: 680; Lead Style: SMT; MFG: Panasonic; Manufacturer: Panasonic; Material: chip; P/D_NUM: ERJ-2RKF1002X; Part Number: ERJ-2RKF1002X; Power: 1/16W; SOURCE: DIGI P10.0KLCT-ND; Tolerance: 1%; Type: resistor; VPC: 1/16W; Vendor: Panasonic
R502-R504 R506 R512 = PAS,R,large: RES 30.1 OHM 1/10W 1% 0402 SMD; Family: passive; Index PN: 1167; Lead Style: SMT; Manufacturer: Panasonic; Part Number: ERJ-2RKF30R1X; SOURCE: DIGI P30.1LCT-ND; TOLERANCE: 1%; Type: resistor; VENDOR: Panasonic
U13 = SN74LVC1G125_0: IC BUS BUFF TRI-ST N-INV 6SON; Manufacturer: Texas Instruments; Source: DIGI 296-21816-1-ND
U14 = W25Q16D: IC FLASH 64MBIT 104MHZ 8WSON; Manufacturer: Winbond; SOURCE: DIGI W25Q64FVZPIG-ND
U501 = OSCILLATOR: OSC XO 24.000MHZ HCMOS SMD; Manufacturer: ECS; P/D_NUM: ECS-2033-240-BN; Part Number: ECS-2033-240-BN; SOURCE: DIGI XC1432CT-ND
C13 C15 = CAP_NP: CAP CER 10000PF 25V 10% X5R 0402; MFG: KEMET; Manufacturer: TDK; Part Number: C1005X5R1E103K050BA; RATING: 25V; SOURCE: DIGI 445-7386-1-ND; TOLERANCE: 10%; Type: X5R
C21 C22 = CAP_NP: CAP CER 10UF 6.3V 20% X5R 0402; MFG: TDK; Manufacturer: TDK; Part Number: C1005X5R0J106M050BC; RATING: 6.3V; SOURCE: DIGI 445-8920-1-ND; TOLERANCE: 20%; Type: X5R
C26 C534 C542 C549 = CAP_NP: CAP CER 10UF 16V 20% X5R 0603; MFG: TDK; Manufacturer: TDK; Part Number: C1608X5R1C106M080AB; RATING: 16V; SOURCE: DIGI 445-9065-1-ND; TOLERANCE: 20%; Type: X5R
C522 C526 C527 = PAS,CAP,NP,large: CAP CER 0.22UF 25V 10% X5R 0402; DigiKey: 445-3446-1-ND; DigiReel: 445-3446-6-ND; Family: passive; Index PN: 1173; Lead Style: SMT; MFG: TDK; Manufacturer: TDK; Material: y5v; P/D_NUM: C1005Y5V1E224Z; Part Number: C1005X5R1E224K050BC; Part Specific: CAP CER 0.22UF 25V Y5V 0402; SOURCE: DIGI 445-5944-1-ND; Type: capacitor; VENDOR: TDK; VPC: 25V; Voltage: 25V
C525 = CAP_NP: CAP CER 2.2UF 16V 10% X5R 0402; MFG: MURATA; Manufacturer: TDK; Part Number: C1005X5R1C225K050BC; RATING: 16V; SOURCE: DIGI 445-9085-1-ND; TOLERANCE: 10%; Type: X5R
C528 C532 = CAP_NP: CAP CER 1UF 16V 10% X5R 0402; MFG: TDK; Manufacturer: Murata; Part Number: C1005X5R1C105K; RATING: 16V; SOURCE: DIGI 445-4978-1-ND; TOLERANCE: 10%; Type: X7R; VPC: 16V; Voltage: 16V
C75 C530 = CAP_18PF_COG_50V_5%_0402: CAP CER 4.7UF 10V 10% X5R 0402; Manufacturer: TDK; Part Number: C1005X5R1A475K050BC; RATING: 10V; SOURCE: DIGI 445-13820-1-ND; TOLERANCE: 10%; Type: X5R
C538 C539 = CAP0805: CAP CER 22UF 16V 20% X5R 0805; Manufacturer: Taiyo Yuden; Part Number: EMK212BBJ226MG-T; Rating: 16V; Reference Designator: C541; Source: DIGI 587-3239-6-ND; Tolerance: 20%; Type: X5R
C540 = CAP_NP: CAP CER 10UF 16V 20% X5R 0603; MFG: TDK; Manufacturer: TDK; Part Number: C1608X7R1C105K080AC; RATING: 16V; SOURCE: DIGI 445-1604-1-ND; TOLERANCE: 20%; Type: X5R
D500 = PAS,DIODE,SCHOTTKY,large: DIODE SCHOTTKY 40V 0.5A SOD123; DigiKey: 568-4131-1-ND; DigiReel: 568-4131-6-ND; Family: passive; Index PN: 907; Lead Style: SMT; MFG: ST Semiconductors; Manufacturer: ST Semiconductors; Part Specific: SCHOTTKY RECT 40V 0.4A SOD123; SOURCE: DIGI 497-7538-1-ND; Type: diode,schottky; VENDOR: ST Semiconductors; VPC: 40V; Voltage: 40V
J501 = CONN_5n_1p0mm: CONN HEADER SH 5POS SIDE 1MM TIN; Manufacturer: JST; SOURCE: DIGI 455-1805-1-ND
L500 = PAS,INDUCTOR,_large: INDUCTOR 2.2UH 20% 1300MA 1008; DigiKey: 490-5114-1-ND; DigiReel: 490-5114-6-ND; Family: passive; Index PN: 1149; Lead Style: SMT; MFG: Murata; Manufacturer: Murata; P/D_NUM: LQM2HPN2R2MG0L; Part Number: LQM2HPN2R2MG0L; Part Specific: INDUCTOR 2.2UH 20% 1300MA 1008; SOURCE: DIGI 490-5114-1-ND; Type: inductor; VENDOR: Murata
L501 = PAS,INDUCTOR,_large: INDUCTOR 10UH 20% 0805 SMD; DigiKey: 587-1632-1-ND; DigiReel: 587-1632-6-ND; Family: passive; Index PN: 901; Lead Style: SMT; MFG: Taiyo Yuden; Manufacturer: Taiyo Yuden; P/D_NUM: CBL2012T100M; Part Number: CBL2012T100M; Part Specific: INDUCTOR 10UH 20% 0805 SMD; SOURCE: DIGI 587-1632-1-ND; Type: inductor; VENDOR: Taiyo Yuden
MH1-MH3 = PL_MTG_2-56: 2-56 Plated Through Hole; Manufacturer: NA; Part Number: NA
R2 R4 = PAS,R,large: RES 30K OHM 1/10W 1% 0402 SMD; Family: passive; Index PN: 680; Lead Style: SMT; MFG: Panasonic; Manufacturer: Panasonic; Material: chip; P/D_NUM: ERJ-2RKF3002X; Part Number: ERJ-2RKF3002X; Power: 1/16W; SOURCE: DIGI P30.0KLCT-ND; Tolerance: 1%; Type: resistor; VPC: 1/16W; Vendor: Panasonic
R3 R7 = PAS,R,large: RES SMD 1K OHM 1% 1/10W 0402; Family: passive; Index PN: 680; Lead Style: SMT; MFG: Panasonic; Manufacturer: Panasonic; Material: chip; P/D_NUM: ERJ-2RKF1001X; Part Number: ERJ-2RKF1001X; Power: 1/10W; SOURCE: DIGI P1.00KLCT-ND; Tolerance: 1%; Type: resistor; VPC: 1/10W; Vendor: Panasonic
R8 = PAS,R,large: RES 270 OHM 1/10W 1% 0402 SMD; Family: passive; Index PN: 1053; Lead Style: SMT; MFG: Panasonic; Manufacturer: Panasonic; Material: chip; Part Number: ERJ-2RKF2700X; Part Specific: RES 300 OHM 1/10W 1% 0402 SMD; SOURCE: DIGI P270LCT-ND; TOLERANCE: 1%; Type: resistor; VPC: 1/16W; Vendor: Panasonic
R9 = PAS,R,large: RES 10K OHM 1/10W 1% 0402 SMD; Family: passive; Index PN: 680; Lead Style: SMT; MFG: Panasonic; Manufacturer: Panasonic; Material: chip; Part Number: ERJ-2RKF1002X; Power: 1/16W; SOURCE: DIGI P10.0KLCT-ND; Tolerance: 1%; Type: resistor; VPC: 1/16W; Vendor: Panasonic
R507 = PAS,R,large: RES 100K OHM 1/10W 1% 0402 SMD; Family: passive; Index PN: 712; Lead Style: SMT; MFG: Panasonic; Manufacturer: Panasonic; Material: chip; P/D_NUM: ERJ-2RKF1003X; Part Number: ERJ-2RKF1003X; Power: 1/16W; SOURCE: DIGI P100KLCT-ND; TOLERANCE: 1%; Type: resistor; VPC: 1/16W; Vendor: Panasonic
U503 = PAD_0: Part Number: DLPC2005RSLR
J503 = CONN_8n_1p0mm: CONN HEADER SH 8POS SIDE 1MM TIN; Manufacturer: JST; SOURCE: DIGI 455-1808-1-ND
L502 = IND0402: Ferrite Bead; Manufacturer: Wurth Electronics; Manufacturer Part Number: 742841210; Part Number: 742841210; Source: DIGI 732-2363-1-ND
R515 = RESISTOR_dsize: RES 0.1 OHM 1/4W 1% 0603 SMD; Digikey Part Number: P100LJCT-ND; Manuf Part Number: ERJ-L03KF10CV; Manufacturer: Panasonic; Part Number: ERJ-L03KF10CV; Source: DIGI P100LJCT-ND
R517 = PAS,R,large: RES SMD 38.3K OHM 1% 1/10W 0402; DigiKey: P38.3KLCT-ND; DigiReel: P38.3KLCT-ND; Family: passive; Index PN: 680; Lead Style: SMT; MFG: Panasonic; Manufacturer: Panasonic; Material: chip; P/D_NUM: ERJ-2RKF1002X; Part Number: ERJ-2RKF3832X; Power: 1/16W; SOURCE: DIGI P38.3KLCT-ND; Tolerance: 1%; Type: resistor; VPC: 1/10W; Vendor: Panasonic
R518 = PAS,R,large: RES 10K OHM 1/16W 1% 0402 SMD; DigiKey: P10KDCCT-ND; DigiReel: P10KDCR-ND; Family: passive; Index PN: 680; Lead Style: SMT; MFG: Panasonic; Manufacturer: Panasonic; Material: chip; P/D_NUM: ERA-2AEB103X; Part Number: ERA-2AEB103X; Power: 1/16W; SOURCE: DIGI P10KDCCT-ND; Tolerance: 0.1%; Type: resistor; VPC: 1/16W; Vendor: Panasonic
R519 = PAS,R,large: RES 3.9K OHM 1/16W 1% 0402 SMD; DigiKey: P3.9KDCCT-ND; DigiReel: P3.9KDCCT-ND; Family: passive; Index PN: 680; Lead Style: SMT; MFG: Panasonic; Manufacturer: Panasonic; Material: chip; P/D_NUM: ERA-2AEB392X; Part Number: ERA-2AEB392X; Power: 1/16W; SOURCE: DIGI P3.9KDCCT-ND; Tolerance: 0.1%; Type: resistor; VPC: 1/16W; Vendor: Panasonic
R520 = PAS,R,large: RES 20 OHM 1/10W 1% 0402 SMD; DigiKey: P20.0LCT-ND; DigiReel: P20.0LR-ND; Family: passive; Index PN: 680; Lead Style: SMT; MFG: Panasonic; Manufacturer: Panasonic; Material: chip; P/D_NUM: ERJ-2RKF20R0X; Part Number: ERJ-2RKF20R0X; Power: 1/10W; SOURCE: DIGI P20.0LCT-ND; Tolerance: 1%; Type: resistor; VPC: 1/10W; Vendor: Panasonic
U504 = TPS81256SIPR
U505 = INA138NA_0: IC OPAMP CURR SENSE 14KHZ SC70-6; Source: DIGI INA213BIDCKT-ND
U506 = OPA454AI_DDA8_1: IC OPAMP GP 1.2MHZ RRO 12VQFN; Manufacturer: Texas Instruments; Part Number: OPA567AIRHGT; Source: DIGI 296-18697-1-ND

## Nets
5V_OUT: C75.2 C544.1 C545.1 C546.1 C547.1 L502.1 U504.A3(VOUT0) U504.B3(VOUT1) U504.C3(VOUT2) U505.3(V+) U506.1(V+) U506.12(V+) U508.5(VCC)
GND: C1.2 C2.2 C3.2 C4.2 C5.2 C6.2 C7.2 C8.2 C9.2 C10.2 C11.2 C12.2 C13.2 C14.2 C15.2 C16.2 C17.2 C18.2 C19.2 C20.2 C21.2 C22.2 C23.2 C24.2 C25.2 C26.2 C27.2 C29.2 C75.1 C500.2 C501.2 C502.2 C503.2 C504.2 C505.2 C506.2 C507.2 C508.2 C509.2 C510.2 C511.2 C512.2 C513.2 C514.2 C515.2 C516.2 C517.2 C518.2 C519.2 C520.2 C521.2 C522.1(P) C524.2 C525.2 C526.1(P) C527.2(N) C528.2 C530.1 C531.2 C532.2 C533.2 C534.2 C535.2 C536.2 C537.2 C538.2 C539.2 C540.2 C541.2 C542.2 C543.1 C544.2 C545.2 C546.2 C547.2 C548.2 FB501.1 J1.5(P5) J1.6(P6) J1.9(P9) J1.10(P10) J1.19(P19) J1.20(P20) J1.33(P33) J1.34(P34) J1.43(P43) J1.44(P44) J1.49(P49) J1.50(P50) J1.59(P59) J1.60(P60) J1.69(P69) J1.70(P70) J1.79(P79) J1.80(P80) J500.3 J500.6 J500.9 J500.10 J500.11 J501.5 J501.6 J501.7 J502.5(P5) J502.6(P6) J502.11(P11) J502.16(P16) J502.17(P17) J502.23(P23) J502.29(P29) J503.9 J503.10 MH1.1 MH2.1 MH3.1 R1.1(N1) R3.1(N1) R7.1(N1) R11.1(N1) R12.1(N1) R500.1(N1) R501.1(N1) R505.1(N1) R514.1(N1) R515.2 R516.1(N1) R517.1(N1) R519.1(N1) U1.4(GND) U1.7(G) U2.1(1OEz) U2.4(GND) U2.7(2OEz) U3.3(GND) U4.3(GND) U5.4(GND) U6.1(1OEz) U6.4(GND) U6.7(2OEz) U7.C4(VSS) U7.C6(VSS) U7.C8(VSS) U7.C10(HWTEST_EN) U7.D6(VSS) U7.D8(VSS) U7.D10(VSS) U7.E4(VSS) U7.E13(VSS) U7.F4(VSS) U7.F6(VSS) U7.F7(VSS) U7.F8(VSS) U7.F9(VSS) U7.F10(VSS) U7.G4(VSS) U7.G6(VSS) U7.G7(VSS) U7.G8(VSS) U7.G9(VSS) U7.G10(VSS) U7.G12(VSS) U7.G13(VSS) U7.H4(VSS) U7.H6(VSS) U7.H7(VSS) U7.H8(VSS) U7.H9(VSS) U7.H10(VSS) U7.H12(VSS) U7.J3(VSS) U7.J6(VSS) U7.J7(VSS) U7.J8(VSS) U7.J9(VSS) U7.J10(VSS) U7.J13(VSS) U7.K4(VSS) U7.K6(VSS) U7.K7(VSS) U7.K8(VSS) U7.K9(VSS) U7.K10(VSS) U7.K12(VSS) U7.L3(VSS) U7.M4(VSS) U7.M5(VSS) U7.M8(VSS) U7.M12(VSS) U8.4(GND) U8.7(G) U9.3(GND) U10.3(GND) U11.4(GND) U12.3(GND) U13.3(GND) U14.4(VSS) U500.3(GND) U501.2(GND) U502.3(GND) U503.5(AGND1) U503.12(PGNDR) U503.20(GND) U503.23(PGNDC) U503.45(PGNDL_1) U503.46(PGNDL_2) U503.49(THERMAL_PAD) U504.A1(GND1) U504.A2(GND2) U504.B1(GND3) U505.1(REF) U505.2(GND) U505.5(IN-) U506.4(V-) U506.5(V-) U506.13(THPAD) U507.3(GND) U508.3(GND)
V2V5: C525.1 U503.19(V2V5)
V6V: C537.1 U503.35(V6V)
CMP_OUT: U7.A12(CMP_OUT) U503.28(CMP_OUT)
CMP_PWM: R9.2(N2) U7.A15(CMP_PWM)
CON_TIVA_MUX0: U1.5(Y) U3.1(A) U3.2(B)
CON_TIVA_MUX0_1P8: U3.4(Y) U7.L15(GPIO_17)
CON_TIVA_MUX1: U8.5(Y) U10.1(A) U10.2(B)
CON_TIVA_MUX1_1P8: U7.M14(GPIO_18) U10.4(Y)
CON_TRIG_IN_0: J500.4 U1.1(A)
CON_TRIG_IN_1: J500.5 U8.1(A)
DATAEN_CMD_B: J1.47(P47) U7.P2(DATEN_CMD)
DEN_ARSTZ: R508.2(N2) U7.B1(DMD_DEN_ARSTZ)
DLPC_HOST_IRQ: J1.23(P23) U7.N8(HOST_IRQ)
DLPC_PRE_XLATE0_1P8: U4.1(A) U4.2(B) U7.E14(GPIO_4)
DLPC_PRE_XLATE1_1P8: U7.L14(GPIO_16) U9.1(A) U9.2(B)
DLPC_SPI_CLK: R504.1(N1) U503.7(SPICLK)
DLPC_SPI_CSZ: R502.1(N1) U503.8(SPICSZ)
DLPC_SPI_OUT: R503.1(N1) U503.3(SPIDIN)
DLPC_SPICLK: R504.2(N2) U7.C15(GPIO_1_SPI_CLK)
DLPC_SPICSZ: R502.2(N2) U7.D15(GPIO_3_SPI_CSz)
DLPC_SPIOUT: R503.2(N2) U7.D14(GPIO_2_SPI_DOUT)
DLPC_XLAT0_CON: J500.7 U2.6(1Y)
DLPC_XLAT0_TIVA: J1.39(P39) U2.3(2Y)
DLPC_XLAT1_CON: J500.8 U6.6(1Y)
DLPC_XLAT1_TIVA: J1.41(P41) U6.3(2Y)
DLPC_XLATE0: U2.2(1A) U2.5(2A) U4.4(Y)
DLPC_XLATE1: U6.2(1A) U6.5(2A) U9.4(Y)
DMD_DEN_ARSTZ: J502.10(P10) R508.1(N1)
DMD_HS_CLK_N: J502.13(P13) U7.B7(DMD_HS_CLK_N)
DMD_HS_CLK_P: J502.15(P15) U7.A7(DMD_HS_CLK_P)
DMD_HS_WDATAA_N: J502.3(P3) U7.B11(DMD_HS_WDATAA_N)
DMD_HS_WDATAA_P: J502.1(P1) U7.A11(DMD_HS_WDATAA_P)
DMD_HS_WDATAB_N: J502.7(P7) U7.B10(DMD_HS_WDATAB_N)
DMD_HS_WDATAB_P: J502.9(P9) U7.A10(DMD_HS_WDATAB_P)
DMD_HS_WDATAG_N: J502.27(P27) U7.B4(DMD_HS_WDATAG_N)
DMD_HS_WDATAG_P: J502.25(P25) U7.A4(DMD_HS_WDATAG_P)
DMD_HS_WDATAH_N: J502.21(P21) U7.B3(DMD_HS_WDATAH_N)
DMD_HS_WDATAH_P: J502.19(P19) U7.A3(DMD_HS_WDATAH_P)
DMD_LS_CLK: J502.14(P14) R510.1(N1)
DMD_LS_WDATA: J502.12(P12) R509.1(N1)
FLASH_CLK: U5.3(2Y) U7.A13(SPI0_CLK) U14.6(CLK)
FLASH_CSz: R14.1(N1) U7.A14(SPI0_CSZ0) U11.6(1Y) U14.1(CSz)
FLASH_DI: U5.6(1Y) U7.B13(SPI0_DOUT) U14.5(DI)
FLASH_DI_TIVA: J1.25(P25) U13.4(O)
FLASH_DO: U7.B12(SPI0_DIN) U13.2(I) U14.2(DO)
FLASH_WPz: R12.2(N2) U11.3(2Y) U14.3(WPz)
GPIO11: J501.2 R4.2(N2) U7.H15(GPIO_11)
GPIO13: J501.1 R2.2(N2) U7.J15(GPIO_13)
HSYNC_CS: J1.48(P48) U7.N5(HSYNC_CS)
LED_SEL_0: U7.B15(LED_SEL_0) U503.31(LED_SEL0)
LED_SEL_1: U7.B14(LED_SEL_1) U503.34(LED_SEL1)
LS_CLK: R510.2(N2) U7.A1(DMD_LS_CLK)
LS_RDATA: J502.8(P8) U7.B2(DMD_LS_RDATA)
LS_WDATA: R509.2(N2) U7.A2(DMD_LS_WDATA)
OSC_24_EN: U501.1(EN) U502.4(Y)
P1P1V: C503.1 C506.1 C507.1 C508.1 C509.1 C510.1 C512.1 C514.1 C515.1 C517.1 C518.1 C524.1 C530.2 FB500.1 L500.2 U7.C3(VDDLP12) U7.C5(VDD) U7.D3(VDD) U7.D5(VDD) U7.D7(VDD) U7.D9(VDD) U7.D12(VDD) U7.D13(VDD) U7.E3(VDD) U7.F13(VDD) U7.H13(VDD) U7.J4(VDD) U7.J12(VDD) U7.K3(VDD) U7.L4(VDD) U7.L12(VDD) U7.L13(VDD) U7.M6(VDD) U7.M9(VDD) U7.M10(VDD) U503.29(VCORE)
P1P8V: C5.1 C8.1 J1.11(P11) J1.12(P12) U503.22(LS_IN)
P1P8V_SW: C10.1 C17.1 C19.1 C21.1 C22.1 C500.1 C502.1 C505.1 C516.1 C521.1 C533.1 C536.1 J502.2(P2) J502.4(P4) J502.24(P24) J502.26(P26) J502.28(P28) J502.30(P30) R513.2(N2) U3.5(VCC) U7.C7(VCC) U7.C9(VCC) U7.D4(VCC) U7.E12(VCC) U7.F12(VCC) U7.K13(VCC) U7.M11(VCC) U10.5(VCC) U500.5(VCC) U502.1(A) U502.2(B) U503.21(LS_OUT) U503.32(VSPI)
P3P3V: C3.1 C4.1 C6.1 C7.1 C9.1 C11.1 C12.1 C14.1 C16.1 C23.1 C25.1 C27.1 C29.1 C501.1 C504.1 C511.1 C519.1 C520.1 C531.1 C535.1 C543.2 J1.7(P7) J1.8(P8) R10.2(N2) R13.2(N2) R14.2(N2) U1.8(VCC) U2.8(VCC) U4.5(VCC) U5.8(VCC) U6.8(VCC) U7.D11(VCC_FLSH) U7.M3(VCC_INTF) U7.M7(VCC_INTF) U7.N3(VCC_INTF) U7.N7(VCC_INTF) U8.8(VCC) U9.5(VCC) U11.8(VCC) U12.5(VCC) U13.6(VCC) U14.7(HLDz) U14.8(VCC) U501.4(VCC) U502.5(VCC) U507.5(VCC)
PAD_INTz: J1.29(P29) R513.1(N1) U7.C13(PARKZ) U503.6(INTZ)
PAD_RSTz: J1.31(P31) R11.2(N2) U7.C11(RESETZ) U12.1(A) U12.2(B) U503.4(RESETZ)
PAD_RSTz_P3P3V: J1.28(P28) U5.1(1OEz) U5.7(2OEz) U11.1(1OEz) U11.7(2OEz) U12.4(Y) U13.1(~{OE})
PAD_SPI_OUT: R512.2(N2) U7.C14(GPIO_0_SPI_DIN)
PAD_SPIOUT: R512.1(N1) U503.9(SPIDOUT)
PCLK: J1.45(P45) U7.P3(PCLK)
PDATA_00: J1.51(P51) U7.K2(PDATA_0)
PDATA_01: J1.52(P52) U7.K1(PDATA_1)
PDATA_02: J1.53(P53) U7.L2(PDATA_2)
PDATA_03: J1.54(P54) U7.L1(PDATA_3)
PDATA_04: J1.55(P55) U7.M2(PDATA_4)
PDATA_05: J1.56(P56) U7.M1(PDATA_5)
PDATA_06: J1.57(P57) U7.N2(PDATA_6)
PDATA_07: J1.58(P58) U7.N1(PDATA_7)
PDATA_08: J1.61(P61) U7.R1(PDATA_8)
PDATA_09: J1.62(P62) U7.R2(PDATA_9)
PDATA_10: J1.63(P63) U7.R3(PDATA_10)
PDATA_11: J1.64(P64) U7.P4(PDATA_11)
PDATA_12: J1.65(P65) U7.R4(PDATA_12)
PDATA_13: J1.66(P66) U7.P5(PDATA_13)
PDATA_14: J1.67(P67) U7.R5(PDATA_14)
PDATA_15: J1.68(P68) U7.P6(PDATA_15)
PDATA_16: J1.71(P71) U7.R6(PDATA_16)
PDATA_17: J1.72(P72) U7.P7(PDATA_17)
PDATA_18: J1.73(P73) U7.R7(PDATA_18)
PDATA_19: J1.74(P74) U7.P8(PDATA_19)
PDATA_20: J1.75(P75) U7.R8(PDATA_20)
PDATA_21: J1.76(P76) U7.P9(PDATA_21)
PDATA_22: J1.77(P77) U7.R9(PDATA_22)
PDATA_23: J1.78(P78) U7.P10(PDATA_23)
PROJ_ON: J1.36(P36) R500.2(N2) U500.1(A) U500.2(B) U503.27(PROJ_ON) U507.1(A) U507.2(B)
PROJ_ON_1p8: U7.G14(PROJ_ON_GPIO_8) U500.4(Y)
PWM_IN: R511.1(N1) U503.26(PWM_IN)
PWM_IN_CAP: C24.1 R8.2(N2) R9.1(N1) R511.2(N2)
RC_CHARGE: R8.1(N1) U7.H14(GPIO_10_RC_CHARGE)
REF_VRST: R507.2(N2) U503.16(REF_VRST)
SENSE1: C13.1 R2.1(N1) R3.2(N2) R5.1(N1) U503.33(SENS1)
SENSE2: C15.1 R4.1(N1) R6.1(N1) R7.2(N2) U503.30(SENS2)
SWN: D500.1(P1) L501.1 U503.11(SWN)
SWP: L501.2 U503.13(SWP)
SYS_PWR: C1.1 C2.1 C26.1 C528.1 C532.1 C534.1 C538.1 C539.1 C540.1 C541.1 C542.1 J1.1(P1) J1.2(P2) J1.3(P3) J1.4(P4) U503.1(VINL) U503.2(VINL) U503.10(VINR) U503.18(VINA) U503.25(VINC) U504.C1(VIN0) U504.C2(VIN1)
TIVA_EXP_I2C_SCL: J1.37(P37) J500.1 U508.1(A)
TIVA_EXP_I2C_SDA: J1.35(P35) J500.2 R505.2(N2) U7.N6(3DR)
TIVA_FLASH_CLK: J1.26(P26) U5.5(2A)
TIVA_FLASH_CSz: J1.24(P24) R10.1(N1) U11.2(1A)
TIVA_FLASH_DO: J1.27(P27) U5.2(1A)
TIVA_IIC0_SCL: J1.32(P32) U7.N10(IIC0_SCL)
TIVA_IIC0_SDA: J1.30(P30) U7.N9(IIC0_SDA)
TIVA_TRIG_IN_0: J1.38(P38) U1.2(B)
TIVA_TRIG_IN_1: J1.40(P40) U8.2(B)
TIVA_TRIG_SEL: J1.42(P42) U1.6(~{A}-B) U8.6(~{A}-B)
VBIAS: C513.1 C526.2(N) J502.20(P20) U503.15(VBIAS)
VOFS: C18.1 C527.1(P) J502.18(P18) U503.17(VOFS)
VRST: C20.1 C522.2(N) D500.2(P2) J502.22(P22) R507.1(N1) U503.14(CNTR_VRST)
VSYNC_WE_B: J1.46(P46) U7.P1(VSYNC_WE)
N42220702: C523.1 C529.1 FB500.2 U7.H2(VDD_PLLM) U7.J2(VDD_PLLD)
N42220708: C523.2 C529.2 FB501.2 U7.G3(VSS_PLLM) U7.H3(VSS_PLLD)
N42256080: L500.1 U503.24(SWC)
N42967134: R506.1(N1) U7.H1(PLL_REFCLK_I)
N42967137: R506.2(N2) U501.3(OUT)
N43024746: R501.2(N2) U7.P11(JTAGTRSTZ)
N43110298: R1.2(N2) U7.N4(PDM_CVS_TE)
N43175533: R13.1(N1) U11.5(2A)
N43213313: J501.3 R5.2(N2)
N43213317: J501.4 R6.2(N2)
N43292672: R514.2(N2) U504.B2(EN) U507.4(Y)
N43292972: R516.2(N2) U506.11(ENABLE) U508.4(Y)
N43293074: U506.10(TFLAG) U508.2(B)
N43294175: R517.2(N2) U506.6(ISET)
N43299776: C548.1 L502.2 R518.2(N2)
N43300259: R518.1(N1) R519.2(N2) U506.9(+IN)
N43303113: C549.1 J503.1 J503.2 J503.3 J503.4 U506.2(OUT) U506.3(OUT)
N43312050: J503.5 J503.6 J503.7 J503.8 R515.1 U505.4(IN+)
N43312673: R520.2(N2) U505.6(OUT) U506.8(-IN)
N43333406: C549.2 R520.1(N1)

Not connected (* = marked no-connect by the designer): J1 13(P13) 14(P14) 15(P15) 16(P16) 17(P17) 18(P18) 21(P21) 22(P22); U1 3(~{Y})*; U7 A5(DMD_HS_WDATAF_P)* A6(DMD_HS_WDATAE_P)* A8(DMD_HS_WDATAD_P)* A9(DMD_HS_WDATAC_P)* B5(DMD_HS_WDATAF_N)* B6(DMD_HS_WDATAE_N)* B8(DMD_HS_WDATAD_N)* B9(DMD_HS_WDATAC_N)* C1(DD3P)* C2(DD3N)* C12(SPI0_CSZ1)* D1(DD2P)* D2(DD2N)* E1(DCLKP)* E2(DCLKN)* E15(GPIO_5)* F1(DD1P)* F2(DD1N)* F3(RREF)* F14(GPIO_6)* F15(GPIO_7)* G1(DD0P)* G2(DD0N)* G15(GPIO_9)* J1(PLL_REFCLK_O)* J14(GPIO_12)* K14(GPIO_14)* K15(GPIO_15)* M13(JTAGTMS1)* M15(GPIO_19)* N11(JTAGTMS2)* N12(JTAGTDO2)* N13(JTAGTDO1)* N14(TSTPT_6)* N15(TSTPT_7)* P12(JTAGTCK)* P13(JTAGTDI)* P14(TSTPT_4)* P15(TSTPT_5)* R10(IIC1_SDA)* R11(IIC1_SCL)* R12(TSTPT_0)* R13(TSTPT_1)* R14(TSTPT_2)* R15(TSTPT_3)*; U8 3(~{Y})*; U503 36(RLIM_K)* 37(SW6)* 38(SW5)* 39(SW4)* 40(RLIM)* 41(VLED_1)* 42(VLED_2)* 43(L2_1)* 44(L2_2)* 47(L1_1)* 48(L1_2)*; U506 7(IFLAG)*

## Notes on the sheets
sheet 1
- Low Resisitance Sense Lines
- CRITICAL LAYOUT NECESSARY FOR PARTS IN THIS SECTION
- J503 REMAINS IN ORIGINAL POSITION ON THE BRD FILE.
- PLACE U504, U505, AND U506 CLOSE TOGETHER AND CLOSE TO J503 OUTPUT.
- USE GROUND SHIELDING TO REDUCE NOISE AROUND ALL COMPONENTS.
- LAMP DRIVER
- 7
- 7
sheet 2
- COMPUTER GENERATED DRAWING - DO NOT REVISE MANUALLY
- NOTES, UNLESS OTHERWISE SPECIFIED:
- REVISIONS
- REV
- DESCRIPTION
- DATE
- APPROVED
- 1.
- The netname "V3P3V" represents connection to the +3.3V power buss
- -
- Draft Release
- 07/24/2014
- HPC
- 2.
- The netname "V1P8V" represents connection to the +1.8V power buss
- 3.
- The netname "V1P8V_SW" represents connection to the +1.8V switched power buss
- A
- ECO 2143348: REV A Release
- 4.
- The netname "SYS_PWR" represents connection to the +4.5V power buss.
- 5.
- The netname "VBIAS" represents connection to the +18.0V DMD power buss.
- 6.
- The netname "VOFS" represents connection to the +10.0V DMD power buss.
- 7.
- The netname "VRST" represents connection to the -14.0V  DMD power buss.
- 8.
- The netname "GND" represents connection to the ground plane.
- 9.
- A "Z" suffix on a signal name indicates an active low signal.
- 10.
- All components with designators "U*", "Q*", and "D*" are electrostatic discharge sensitive.
- 11.
- All resistor values are in ohms.
- 12.
- All capacitor values in microfarads unless otherwise specified.
- 7
- ???
- ???
sheet 3
- VCCI
- VCC
- DLPC150 PARALLEL & DMD INTERFACES
- 2
- 7
sheet 4
- DLPC150 MISC & POWER
- 4
- 7
sheet 5
- VOFS= 10.0V
- VBIAS= 18V
- VRST= -14V
- PAD 2005
- 5
- 7
sheet 6
- Revision History
- Rev. -- : Draft Release ~ 07/24/2014
- Rev. A: ECO 2143348: ~ 07/??/2014
- Rev. A: Added three 2-56 mounting holes:  08/22/2014 MR.
- Rev. A: Changed U7 from DLPC150ZEZ to DLPC3435ZEZ: 08/29/2014 MR.
- Rev. A: Changed U503 from DLPC2005 to DLPA2005: 08/29/2014 MR.
- Rev. B: Changed J502 pinout:switched odd/even pins to match DMD board pinout: 10/17/2014 MR.(page2)
- Rev. B: Changed U13 : P3P3V connection to pin6, 10/17/2014 MR.(page4)
- Rev. B: Changed U14 : Changed part to MX25L3206EZUI12G requires new PCB footprint. MR.(page5)
- Rev. B: Changed U503 : Changed symbol SPICLK to pin7 and SPIDIN to pin3. 10/17/2014 MR.(page5)
- Rev. B: Changed C26, C540 to 0603 : C538,C539, C541, C542 to 0805 Changed 10/21/2014 MR.(page5)
- Rev. C: Adderd U7A pinN6 connection to net TIVA_EXP_I2C_SDA 2/7/2015 MR.(page4)
- Rev. C: Removed L502, C541,C28, C542, C30, R516, R518, R517, R515 and J503 traces from PAD2005 2/7/2015 MR.(page5).
- Rev. C: Added Lamp Driver circuit to schematic 2/7/2015 MR.(page7).
- Rev. D: Added C549 and R520 to Lamp Driver circuit U506 output compensation. 3/12/2015 MR.(page7).
- Schematic Revision History
sheet 7
- TIVA - DPP - CONNECTOR - I/O
- 3
- 7
